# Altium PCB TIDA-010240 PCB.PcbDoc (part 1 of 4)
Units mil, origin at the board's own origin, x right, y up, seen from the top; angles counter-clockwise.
Board outline 5108.27 x 5374.02 mil, 4 copper layers (Top Layer, GND, PWR, Bottom Layer), stack 73.068 mil thick; 370 components, 162 nets, 1073 pads, 556 vias.
Unrouted connection lines stored in the file: 6.
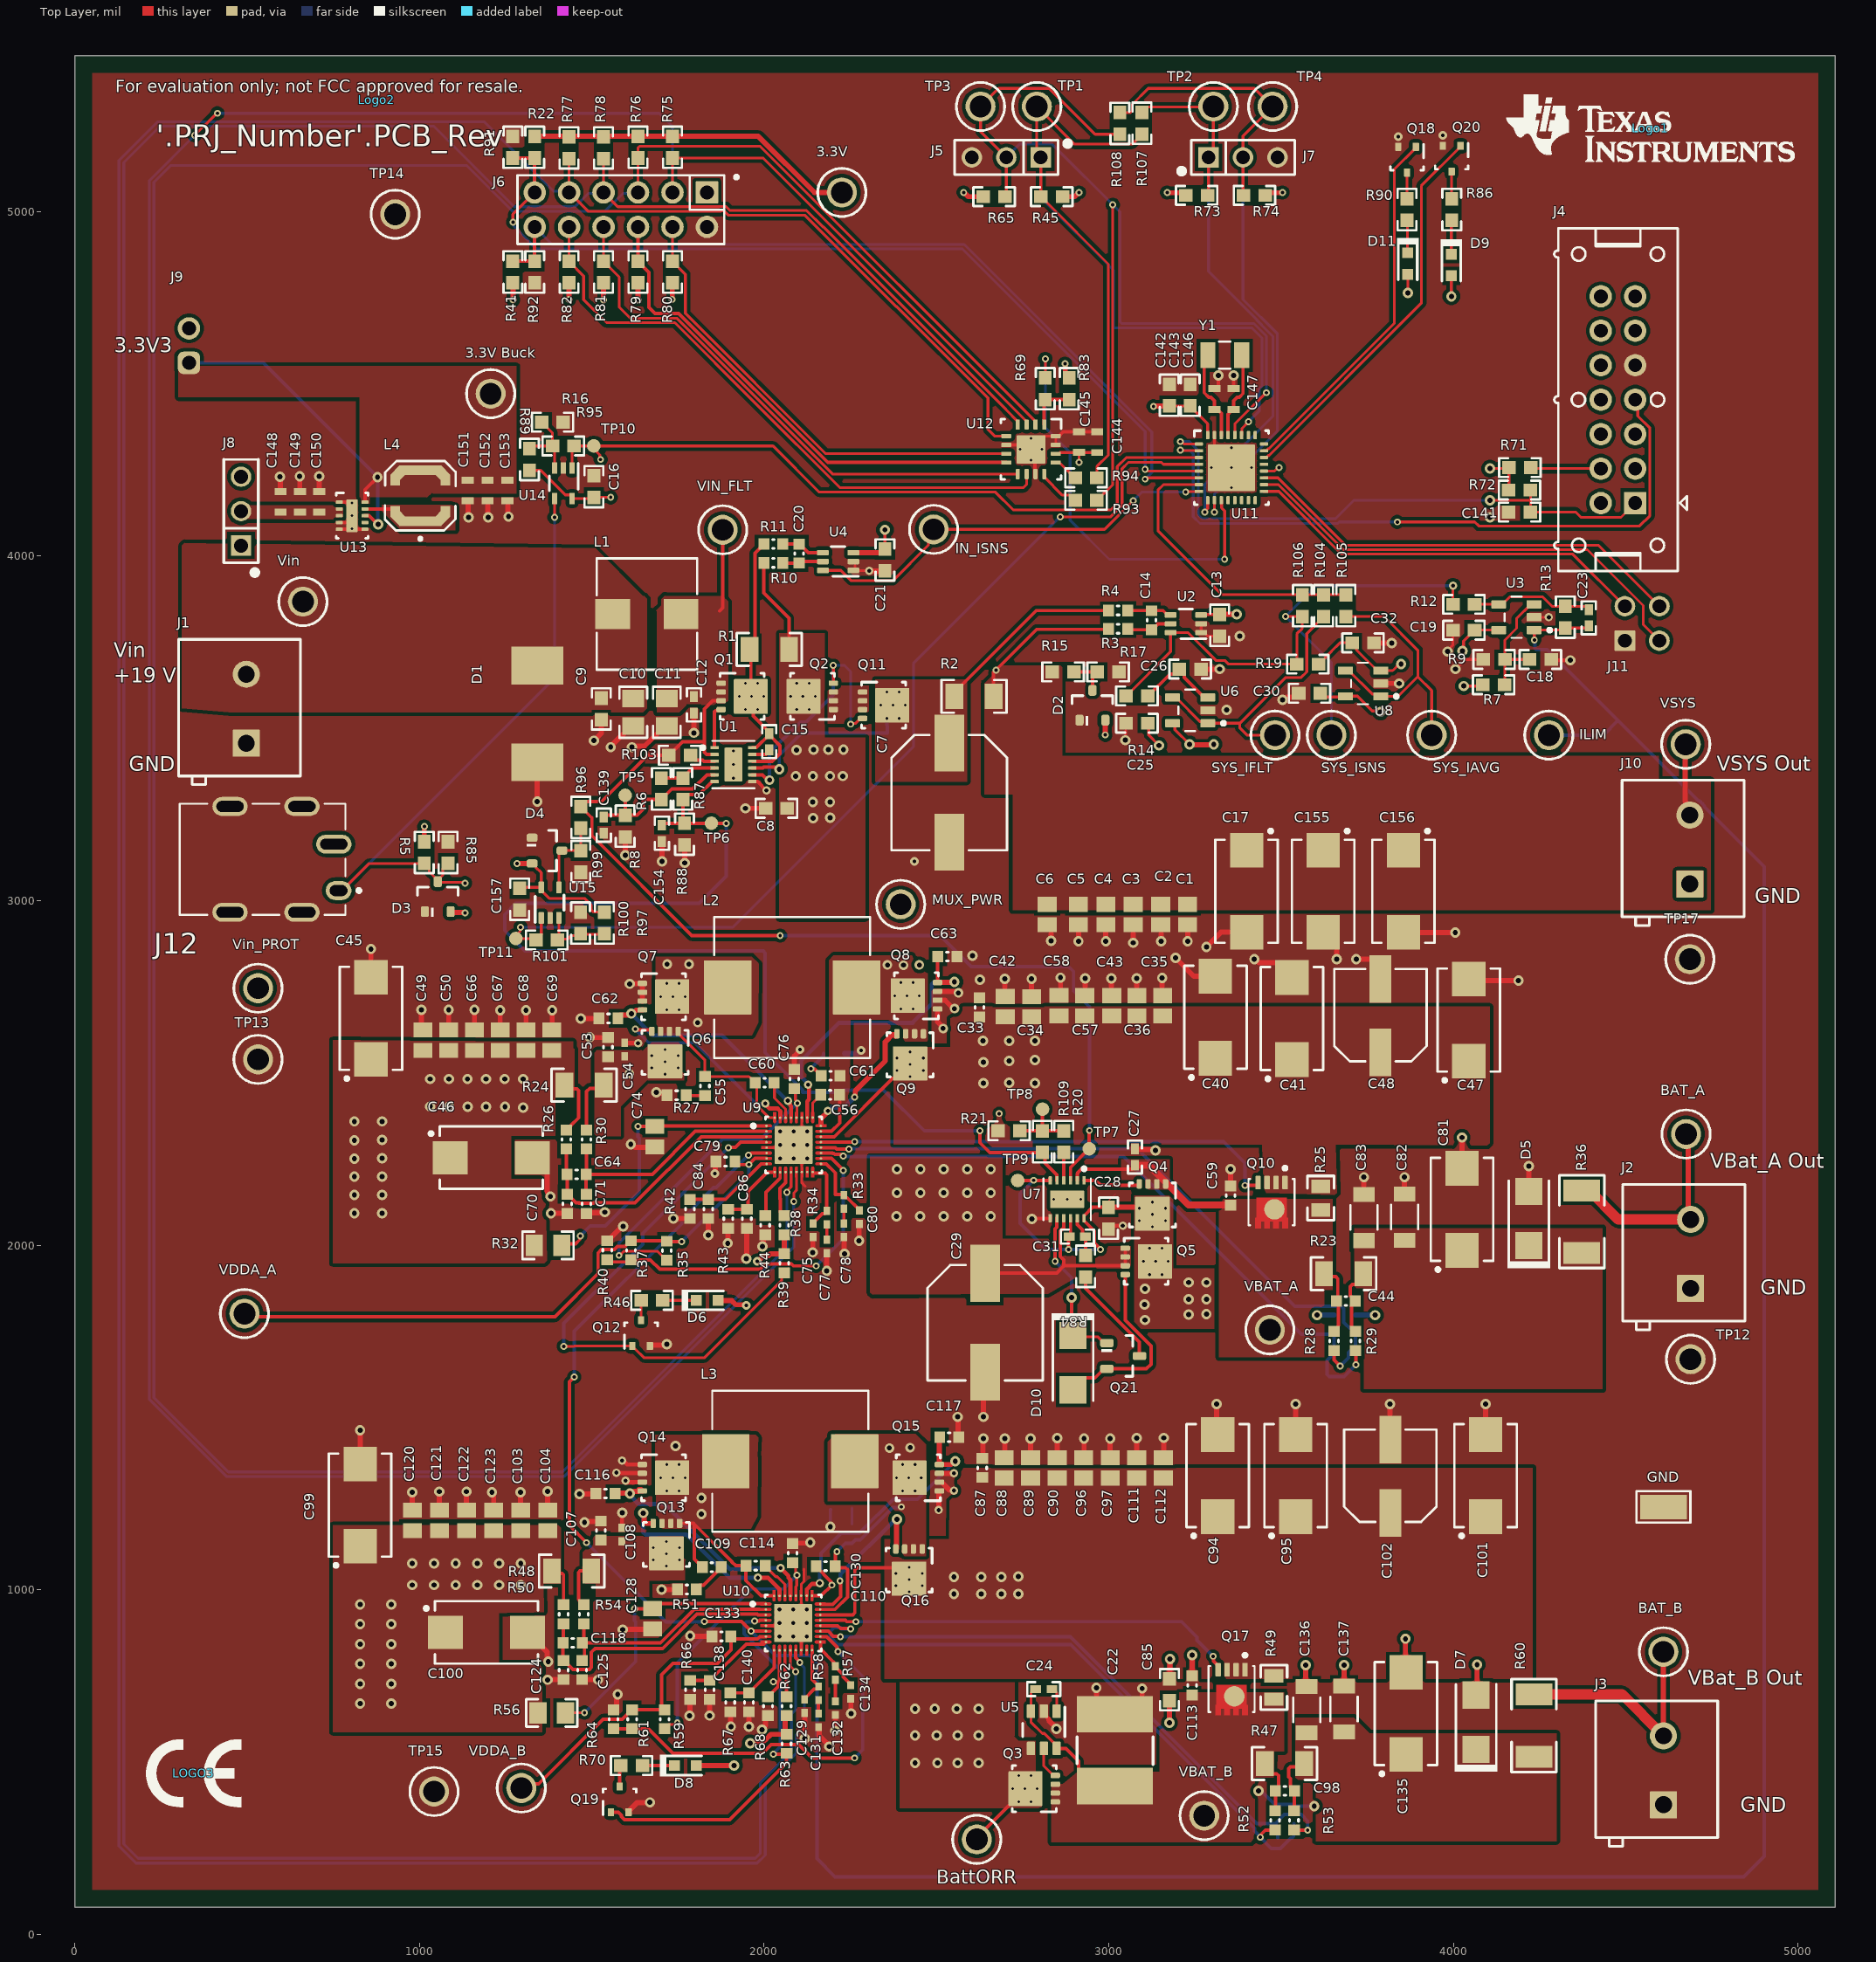
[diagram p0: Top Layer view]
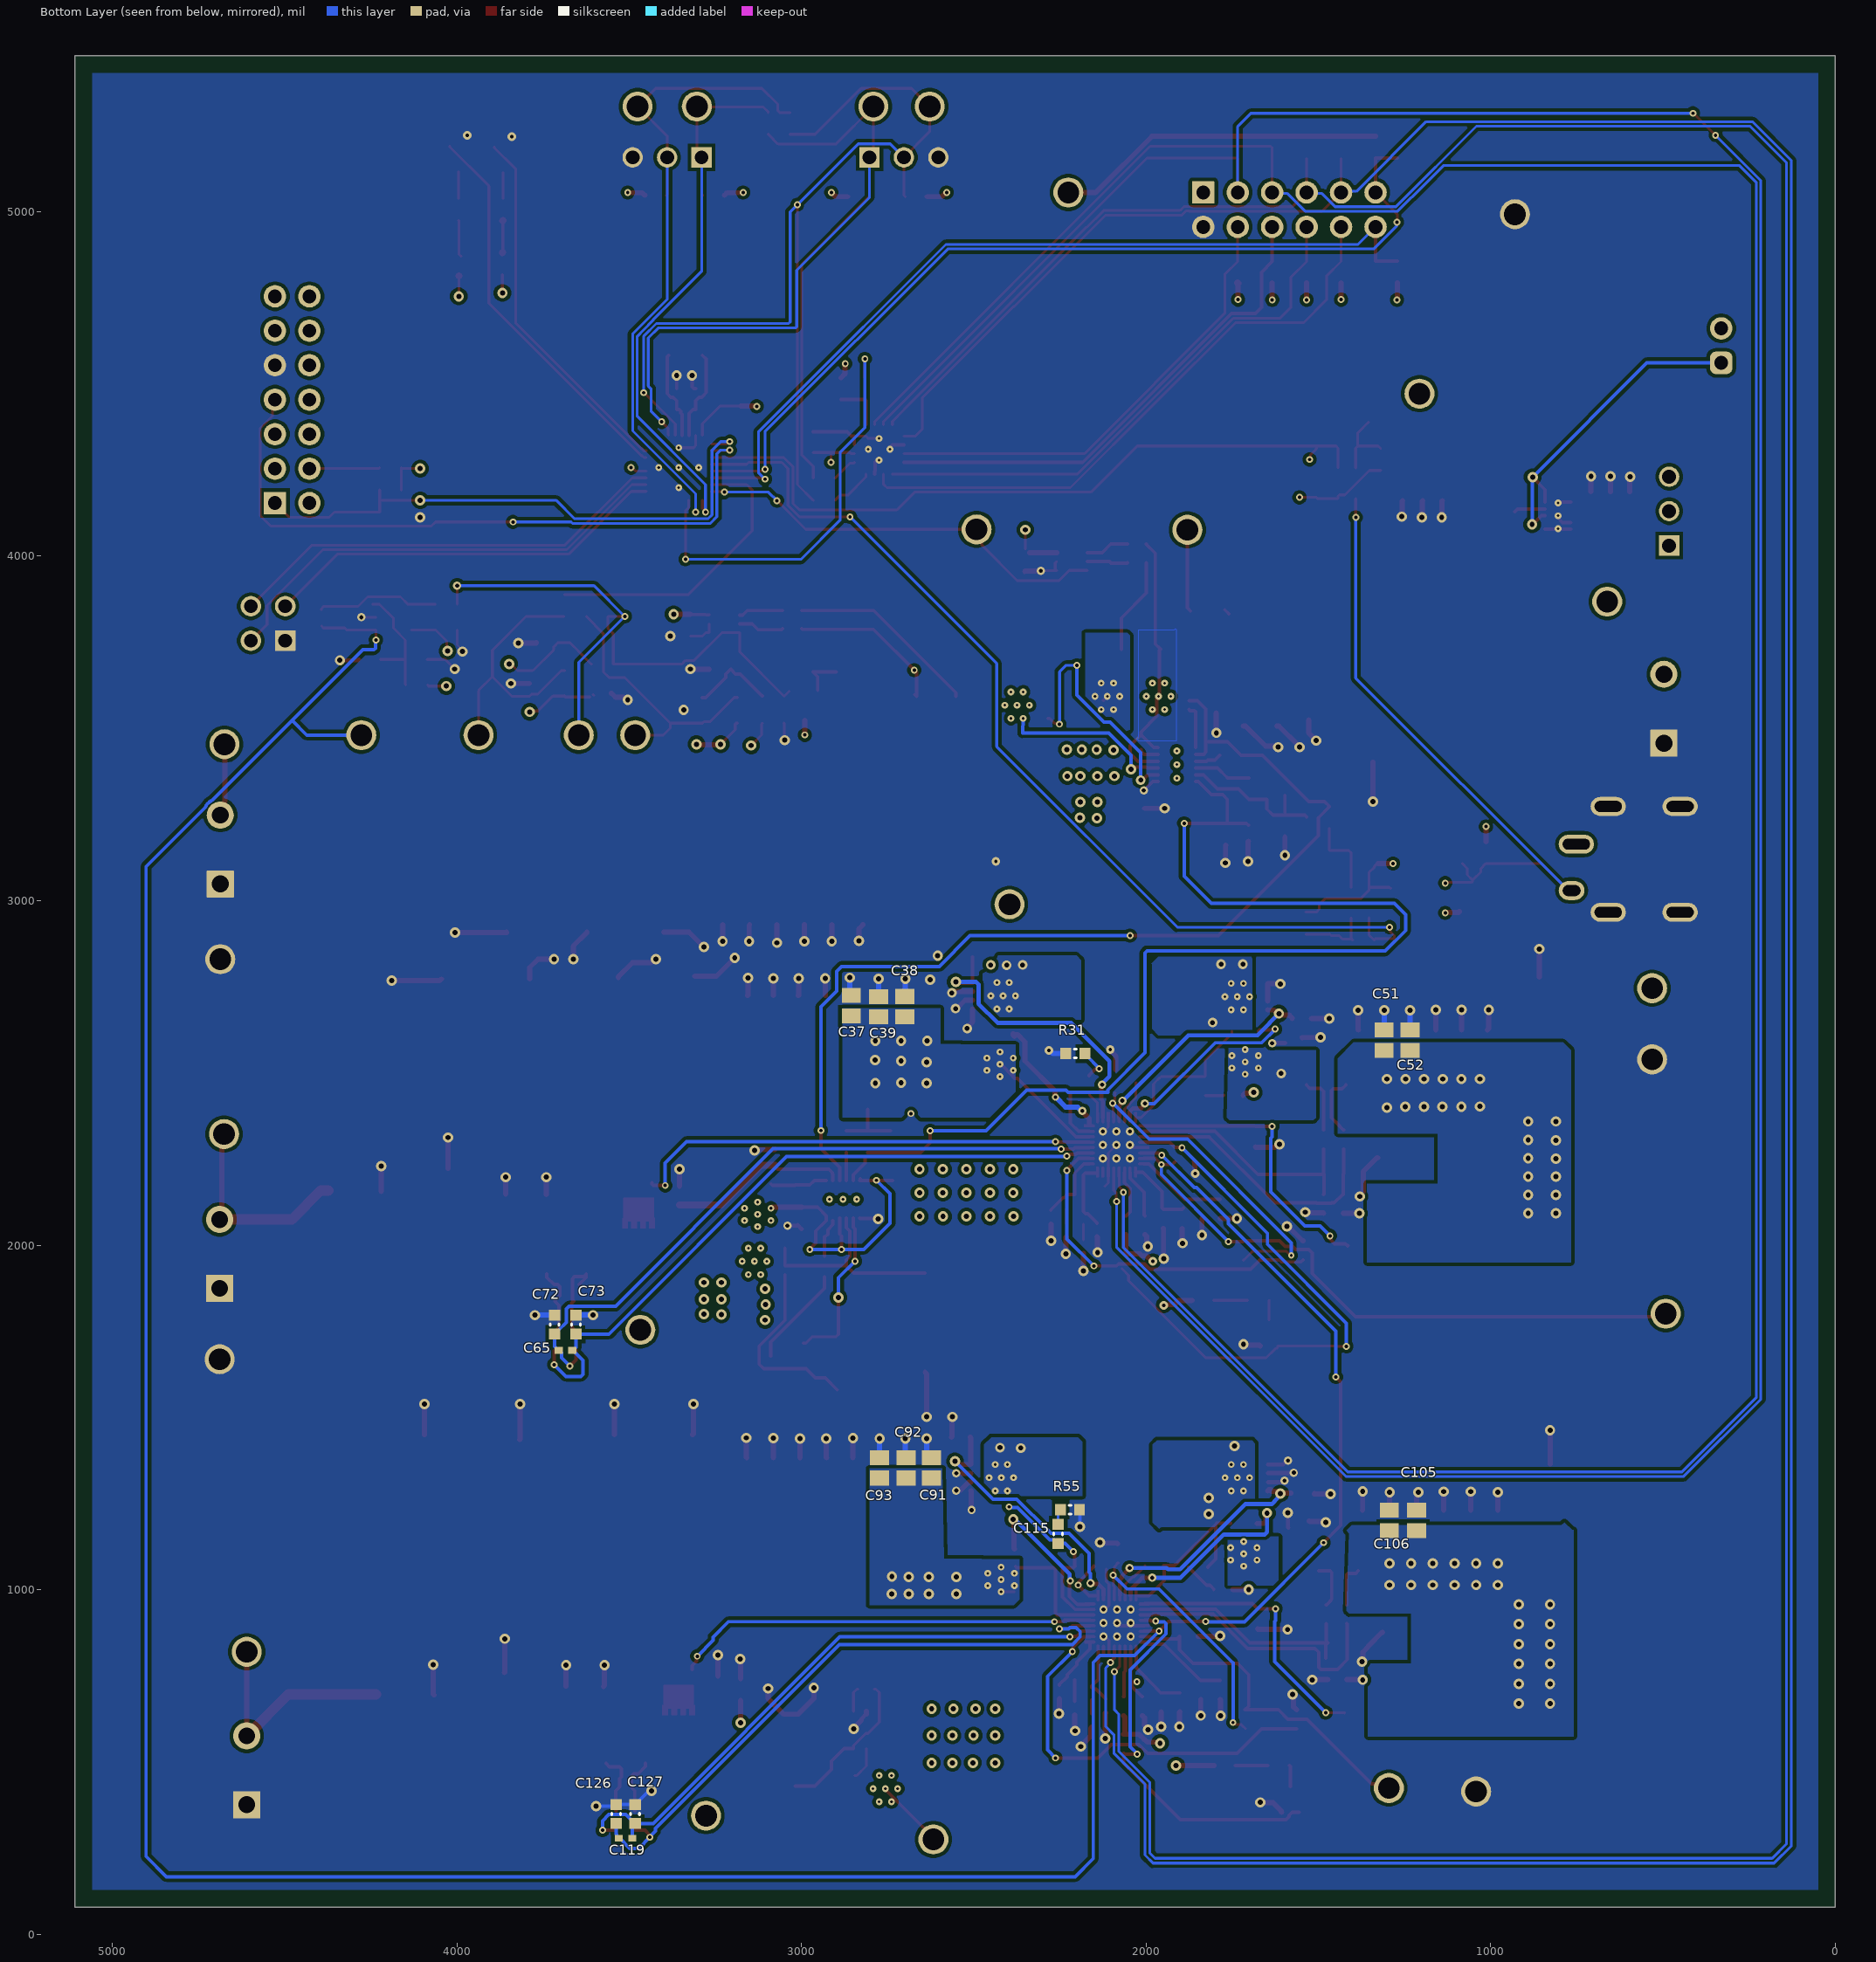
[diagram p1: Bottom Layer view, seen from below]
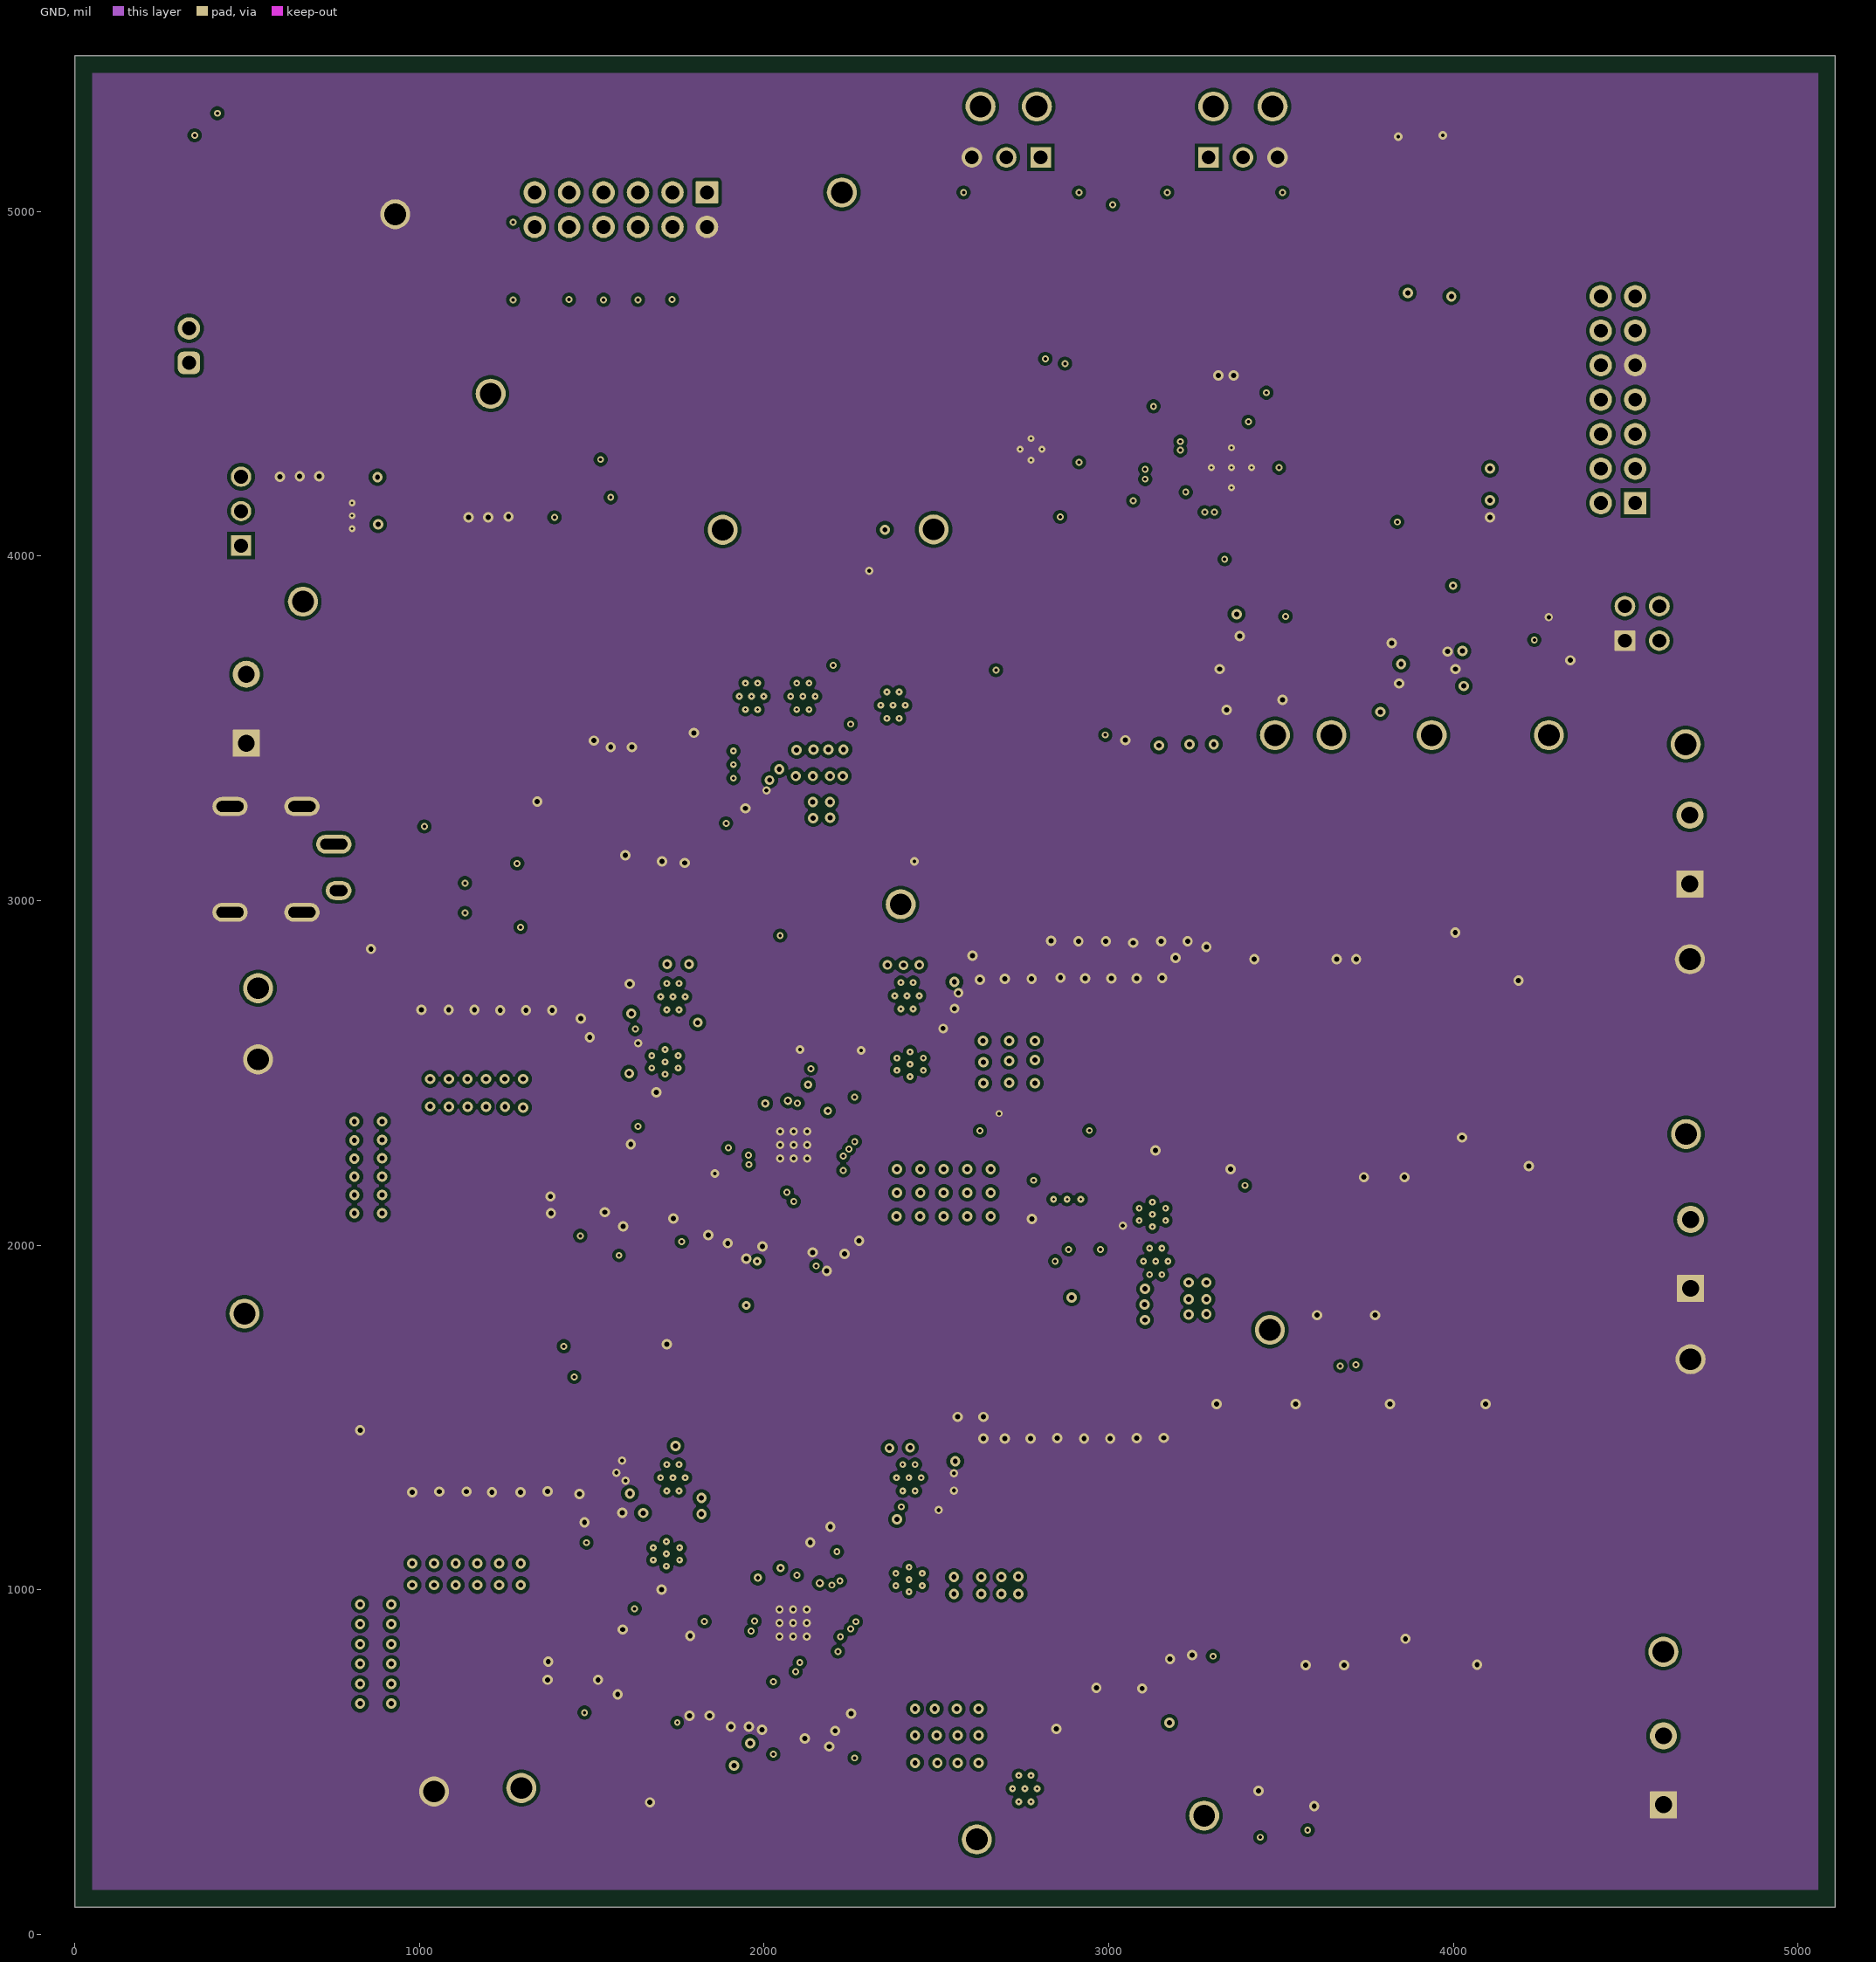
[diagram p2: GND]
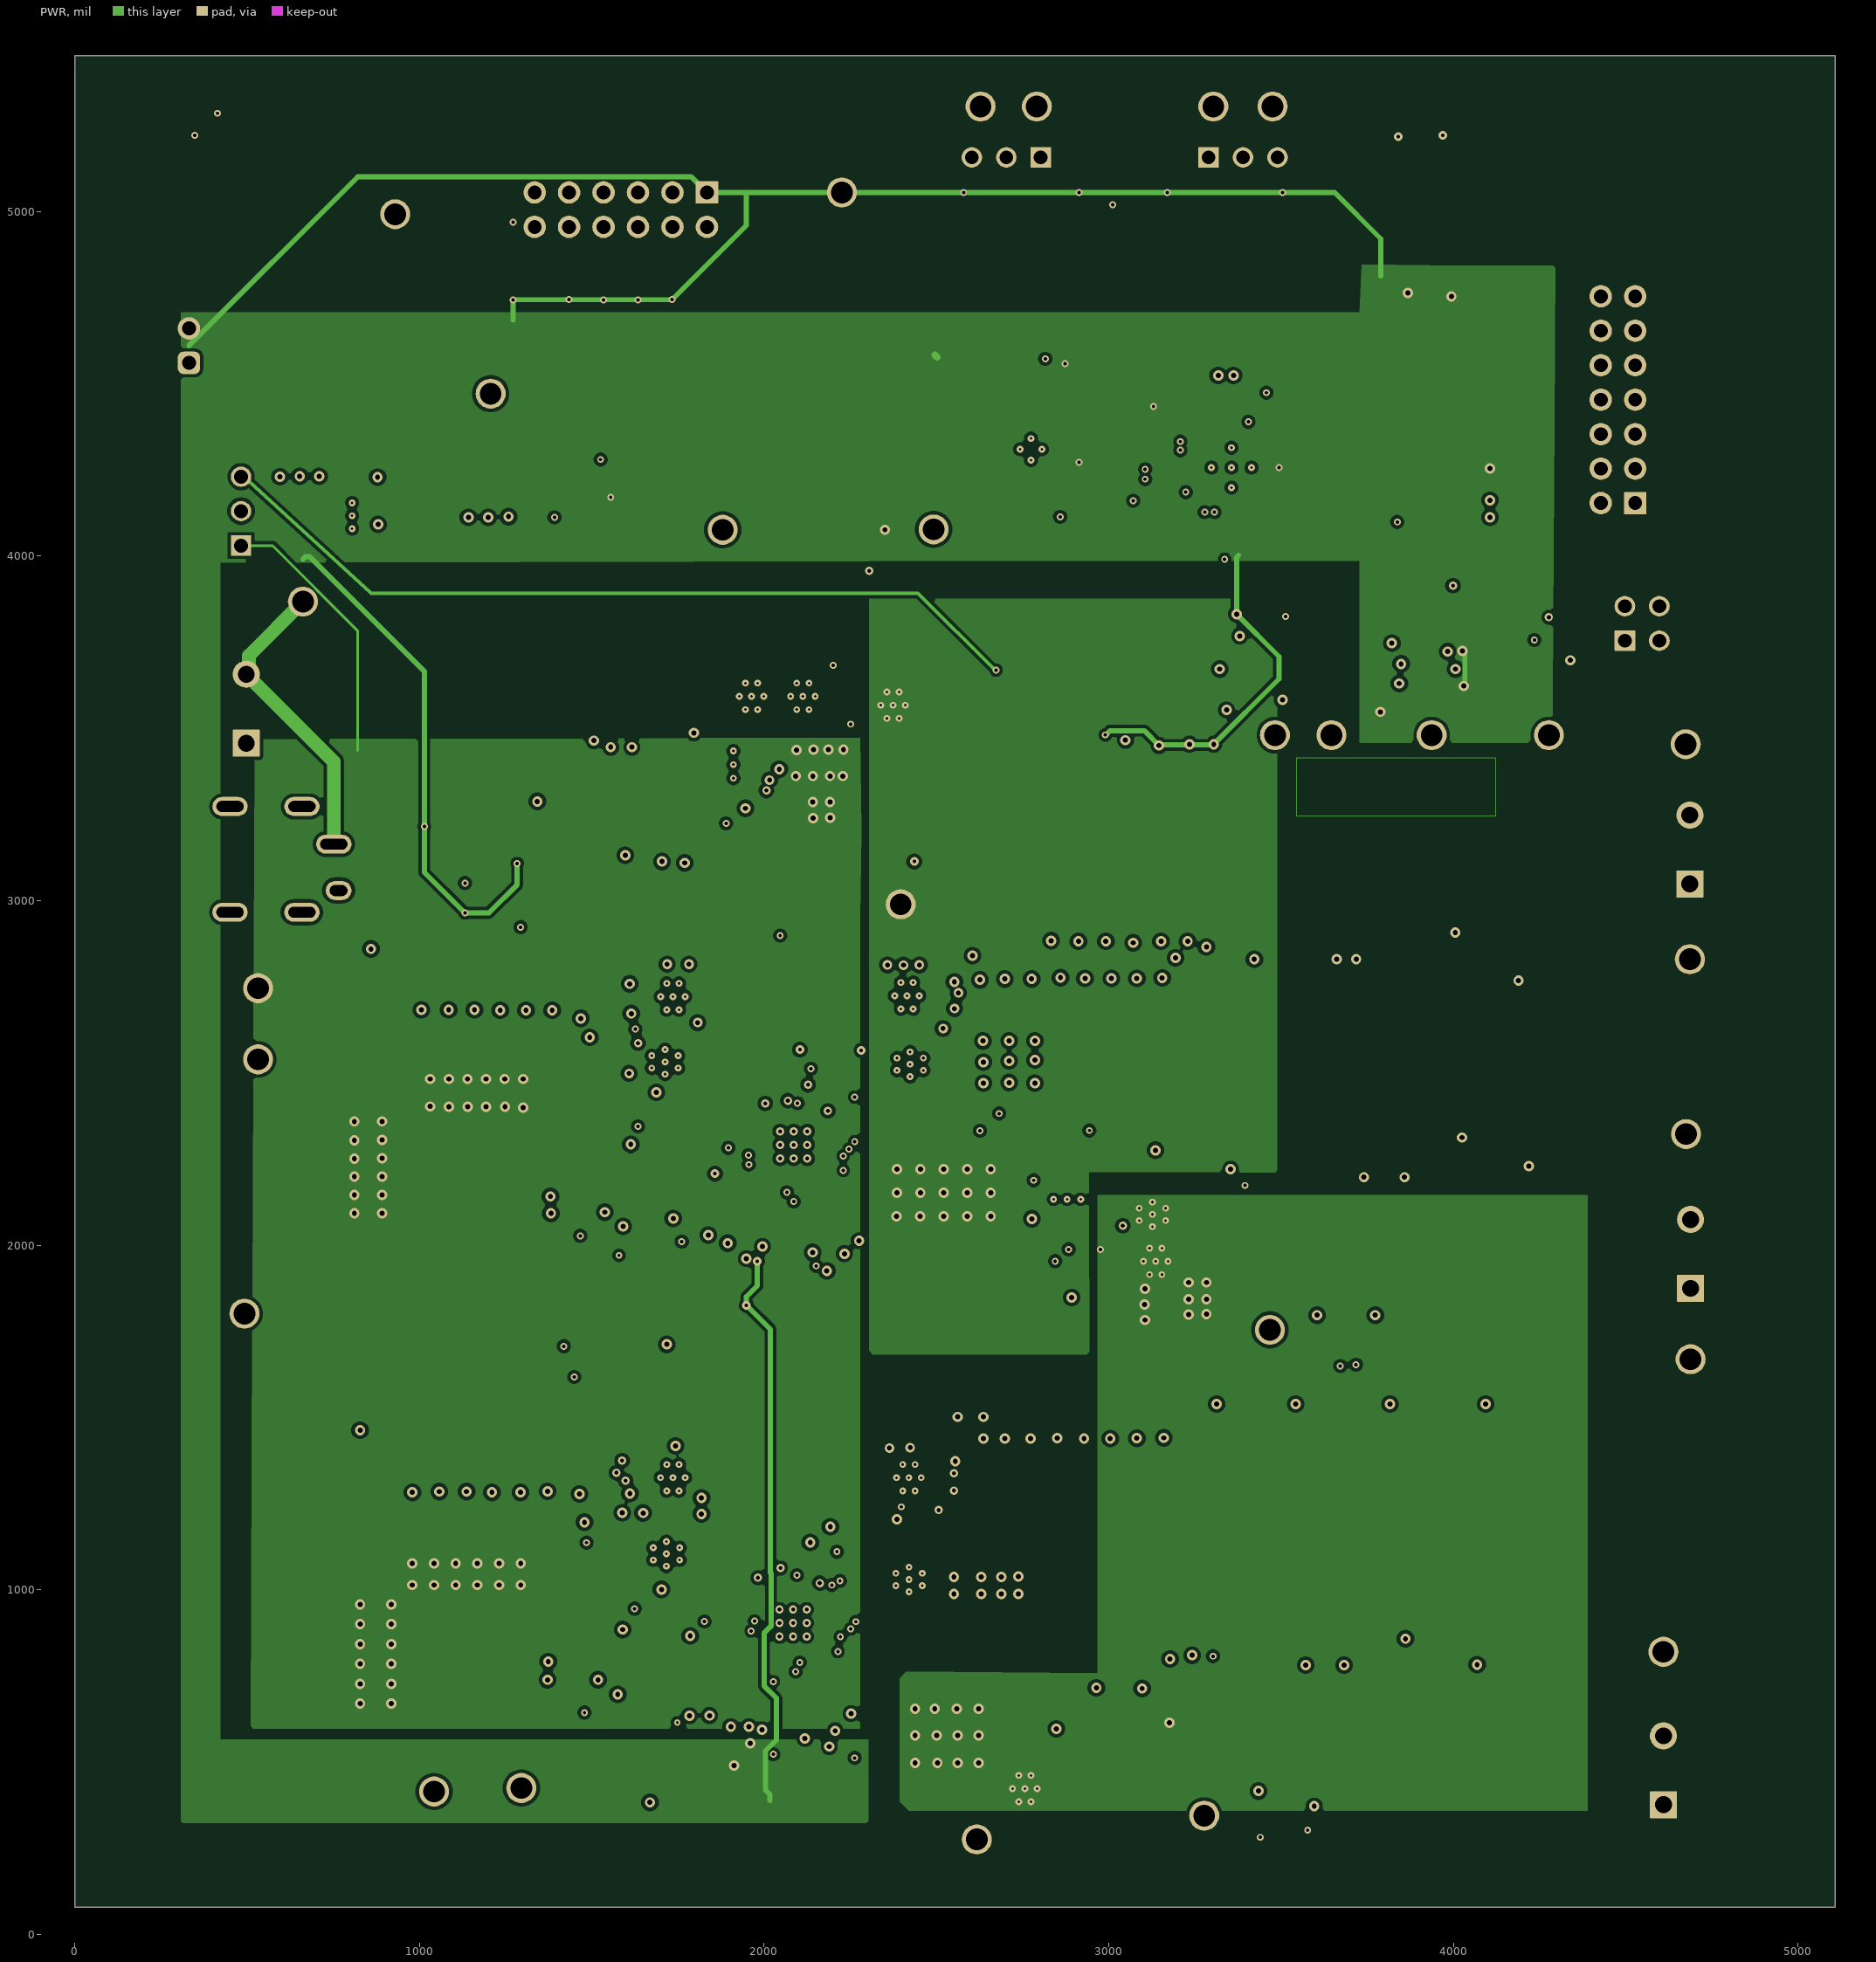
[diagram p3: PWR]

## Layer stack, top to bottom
Top Solder: solder mask 0.4, Solder Resist, Dk 3.5
Top Layer: signal copper 2.7559
Dielectric 1: prepreg 2.8, PP-006, Dk 4.1
GND: signal copper 1.378
Dielectric1: core 59.2, FR-4 High Tg, Dk 4.8
PWR: signal copper 1.378
Dielectric 2: prepreg 2.8, PP-006, Dk 4.1
Bottom Layer: signal copper 2.7559
Bottom Solder: solder mask 0.4, Solder Resist, Dk 3.5

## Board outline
0,78.74 0,5452.76 5108.27,5452.76 5108.27,78.74

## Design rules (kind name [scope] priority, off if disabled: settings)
AcuteAngle [All] p1: minimum=4.50000000000000E+0001 checktracksonly=FALSE
AssemblyTestPointUsage [All] p1: valid=2
BoardOutlineClearance BoardOutlineClearance_MountingHoles [OnCopper and InComponentClass('Mounting Holes')] p1: gap=39.37 ignorepadtopadclearanceinfootprint=FALSE
BoardOutlineClearance BoardOutlineClearance_Poly [OnCopper and IsPoly] p2: gap=50 ignorepadtopadclearanceinfootprint=FALSE
BoardOutlineClearance [OnCopper and Not InComponentClass('Logo') and not InComponentClass('FiducialMark') and not InRegion(1000,500,4000,800) and not InPoly] p3: gap=75 ignorepadtopadclearanceinfootprint=FALSE
Clearance Clearance_Keepouts [((IsTrack Or IsArc) And Not InPoly) And IsFree and IsKeepOut vs ((IsTrack Or IsArc) And Not InPoly) And IsFree and IsKeepOut] p1: gap=0 ignorepadtopadclearanceinfootprint=FALSE
Clearance Clearance_Poly [InPolygon] p2: gap=10 ignorepadtopadclearanceinfootprint=TRUE
Clearance Clearance_FiducialMark [IsKeepOut and InComponentClass('FiducialMark') vs IsPad and InComponentClass('FiducialMark')] p3: gap=0 ignorepadtopadclearanceinfootprint=FALSE
Clearance [All] p4: gap=5 ignorepadtopadclearanceinfootprint=TRUE
ComponentClearance ComponentClearance_MountingHoles_FiducialMarks [InComponentClass('Mounting Holes') vs InComponentClass('FiducialMark')] p1: gap=50 collisioncheckmode=3 verticalgap=10 showdistances=FALSE
ComponentClearance ComponentClearance_Shunt [InComponentClass('Header') vs InComponentClass('Shunt')] p2: gap=0 collisioncheckmode=3 verticalgap=0 showdistances=FALSE
ComponentClearance ComponentClearance_Logo [InComponentClass('Logo')] p3: gap=50 collisioncheckmode=3 verticalgap=10 showdistances=FALSE
ComponentClearance ComponentClearance_ScrewToNut [(HasFootprint('NY PMS 440 0025 PH')) vs (HasFootprint('Keystone_1902C'))] p4: gap=5 collisioncheckmode=3 verticalgap=10 showdistances=FALSE
ComponentClearance ComponentClearance_MountingHoles [InComponentClass('Mounting Holes')] p5: gap=250 collisioncheckmode=3 verticalgap=100000 showdistances=FALSE
ComponentClearance ComponentClearance_SmallPassives [HasFootprint('0201*') or HasFootprint('0402*') or HasFootprint('0508') or HasFootprint('0603*') or HasFootprint('0612') or HasFootprint('0805*') or HasFootprint('0815*') or HasFootprint('0830*') or HasFootprint('1206*') or HasFootprint('1210*') or HasFootprint('1808*') or HasFootprint('1812*') or HasFootprint('1825*') or HasFootprint('2010*') or HasFootprint('2220*') or HasFootprint('2225*') or HasFootprint('2512*') or HasFootprint('2728*') or HasFootprint('3518*') vs HasFootprint('0201*') or HasFootprint('0402*') or HasFootprint('0508') or HasFootprint('0603*') or HasFootprint('0612') or HasFootprint('0805*') or HasFootprint('0815*') or HasFootprint('0830*') or HasFootprint('1206*') or HasFootprint('1210*') or HasFootprint('1808*') or HasFootprint('1812*') or HasFootprint('1825*') or HasFootprint('2010*') or HasFootprint('2220*') or HasFootprint('2225*') or HasFootprint('2512*') or HasFootprint('2728*') or HasFootprint('3518*')] p6: gap=14.96 collisioncheckmode=3 verticalgap=10 showdistances=FALSE
ComponentClearance ComponentClearance_THtoSMT [IsThruComponent vs IsSMTComponent] p7: gap=40 collisioncheckmode=3 verticalgap=30 showdistances=FALSE
ComponentClearance ComponentClearance_THtoTH [IsThruComponent vs IsThruComponent] p8: gap=30 collisioncheckmode=3 verticalgap=30 showdistances=FALSE
ComponentClearance [All] p9: gap=30 collisioncheckmode=3 verticalgap=10 showdistances=FALSE
DiffPairsRouting [All] p1: maxlimit=100 minlimit=10 mostfreqgap=10 toplayer_minwidth=15 toplayer_maxwidth=15 toplayer_prefwidth=15 midlayer1_minwidth=15 midlayer1_maxwidth=15 midlayer1_prefwidth=15 midlayer2_minwidth=15 midlayer2_maxwidth=15 midlayer2_prefwidth=15 bottomlayer_minwidth=15 bottomlayer_maxwidth=15 bottomlayer_prefwidth=15 maxuncoupledlength=1000
FabricationTestPointUsage TestPointUsage [All] p1: valid=2 allowmultiple=FALSE
FabricationTestpoint Testpoint [All] p1: side=3 testpointundercomponent=TRUE minsize=40 maxsize=100 preferedsize=60 minholesize=0 maxholesize=40 preferedholesize=32 testpointgrid=1 allowsidetop=TRUE allowsidebottom=TRUE usegrid=TRUE gridtolerance=0.01
FanoutControl Fanout_LCC [IsLCC] p1: bgadir=Out bgaviamode=Centered fanoutstyle=Auto fanoutdirection=Alternating viagrid=1 // Fanout_LCC (Default Rule)
FanoutControl Fanout_BGA [IsBGA] p2: bgadir=Out bgaviamode=Centered fanoutstyle=Auto fanoutdirection=Alternating viagrid=1 // Fanout_BGA (Default Rule)
FanoutControl Fanout_Default [All] p4: bgadir=Out bgaviamode=Centered fanoutstyle=Auto fanoutdirection=Alternating viagrid=1 // Fanout_Default (Default Rule)
FanoutControl Fanout_Small [(CompPinCount < 5)] p5: bgadir=Out bgaviamode=Centered fanoutstyle=Auto fanoutdirection=OutThenIn viagrid=1 // Fanout_Small (Default Rule)
HoleSize [All] p1: absolutevalues=TRUE maxlimit=251 minlimit=7.87 maxpercent=80.000 minpercent=20.000
MinimumAnnularRing MinimumAnnularRing_ThermalPadVias [IsVia and InAnyComponent] p1: minimumring=5.91
MinimumAnnularRing [All] p2: minimumring=4
MinimumSolderMaskSliver MinimumSolderMaskSliver_Logo [InComponentClass('Logo') vs InComponentClass('Logo')] p1: minsoldermaskwidth=0.7
MinimumSolderMaskSliver [All] p2: minsoldermaskwidth=1.5
PlaneClearance [All] p1: clearance=10
PlaneConnect [All] p1: planeconnectstyle=Relief reliefexpansion=10 reliefentries=4 reliefconductorwidth=10 reliefairgap=10
PolygonConnect [All] p1: connectstyle=Direct reliefconductorwidth=10 reliefentries=4 polygonreliefangle="90 Angle" airgapwidth=10
RoutingVias ThermalPadVias [IsVia and InAnyComponent] p1: holewidth=7.87 width=19.68 viastyle="Through Hole" minholewidth=7.87 minwidth=19.68 maxholewidth=12.99 maxwidth=23.62
RoutingVias [All] p2: holewidth=10 width=18 viastyle="Through Hole" minholewidth=8 minwidth=18 maxholewidth=40 maxwidth=64
SMDEntry [All] p1 off: side=TRUE corner=TRUE anyangle=FALSE
SMDToCorner [All] p1 off: distance=50000
SilkToBoardRegionClearance [Not ((IsComment or IsDesignator) And (Hide <> 'False')) and not InRegion(1000,500,4000,800)] p1:
SilkToSilkClearance SilkToSilkClearance_Pb-FreeLogo [(HasFootprint('Pb-Free_Overlay_Medium') OR HasFootprint('Pb-Free_Overlay_Small')) vs (HasFootprint('Pb-Free_Overlay_Medium') OR HasFootprint('Pb-Free_Overlay_Small'))] p1: silktosilkclearance=0
SilkToSilkClearance [All] p2: silktosilkclearance=0
SilkToSolderMaskClearance SilkToComponentPadClearance [(IsPad or IsFill or IsRegion) and InAnycomponent] p1: minsilkscreentomaskgap=5 clearancetoexposedcopper=TRUE
SilkToSolderMaskClearance "Silk to Solder Mask Opening" [All] p2: minsilkscreentomaskgap=3.94 clearancetoexposedcopper=FALSE
SolderMaskExpansion [All] p1: expansion=4 istentingtop=FALSE
UnRoutedNet [All] p1: checkbadconnections=TRUE
Width [All] p1: maxlimit=100 minlimit=5 preferedwidth=10 checkconnectedcopper=TRUE
13 further rules are at their usual default settings.

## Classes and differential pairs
component class Sensing: C13 C14 C16 C18 C19 C20 C21 C23 C25 C26 C30 C32 C157 D2 D3 D4 ILIM IN_ISNS R3 R4 R5 R7 R9 R10 R11 R12 R13 R14 R15 R16 R17 R19 R85 R89 R95 R96 R97 R99 R100 R101 R104 R105 R106 SYS_IAVG SYS_IFLT SYS_ISNS TP10 TP11 U2 U3 U4 U6 U8 U14 U15
component class BQ25731_A: BAT_A C33 C34 C35 C36 C37 C38 C39 C40 C41 C42 C43 C44 C45 C46 C47 C48 C49 C50 C51 C52 C53 C54 C55 C56 C57 C58 C59 C60 C61 C62 C63 C64 C65 C66 C67 C68 C69 C70 C71 C72 C73 C74 C75 C76 C77 C78 C79 C80 C81 C82 C83 C84 C86 D5 D6 GND J2 L2 Q6 Q7 Q8 Q9 Q10 Q12 R23 R24 R25 R26 R27 R28 R29 R30 R31 R32 R33 R34 R35 R36 R37 R38 R39 R40 R42 R43 R44 R46 TP24 TP34 U9 VDDA_A
component class MSP: 3.3V "3.3V Buck" C141 C142 C143 C144 C145 C146 C147 C148 C149 C150 C151 C152 C153 D9 D11 J4 J5 J6 J7 J8 J9 J11 L4 Q18 Q20 R22 R41 R45 R65 R69 R71 R72 R73 R74 R75 R76 R77 R78 R79 R80 R81 R82 R83 R86 R90 R91 R92 R93 R94 R107 R108 TP1 TP2 TP3 TP4 TP12 TP13 TP14 TP15 TP17 U11 U12 U13 Y1
component class Header: J5 J6 J7 J8 J9
component class BQ25731_B: BAT_B C87 C88 C89 C90 C91 C92 C93 C94 C95 C96 C97 C98 C99 C100 C101 C102 C103 C104 C105 C106 C107 C108 C109 C110 C111 C112 C113 C114 C115 C116 C117 C118 C119 C120 C121 C122 C123 C124 C125 C126 C127 C128 C129 C130 C131 C132 C133 C134 C135 C136 C137 C138 C140 D7 D8 J3 L3 Q13 Q14 Q15 Q16 Q17 Q19 R47 R48 R49 R50 R51 R52 R53 R54 R55 R56 R57 R58 R59 R60 R61 R62 R63 R64 R66 R67 R68 R70 TP52 U10 VDDA_B z
component class InputProtection: BattORR C1 C2 C3 C4 C5 C6 C7 C8 C9 C10 C11 C12 C15 C17 C22 C24 C27 C28 C29 C31 C85 C139 C154 C155 C156 D1 D10 J1 J10 J12 L1 MUX_PWR Q1 Q2 Q3 Q4 Q5 Q11 Q21 R1 R2 R6 R8 R20 R21 R84 R87 R88 R103 R109 TP5 TP6 TP7 TP8 TP9 U1 U5 U7 VBAT_A VBAT_B Vin VIN_FLT Vin_PROT VSYS
component class Logo: Logo1
component class PCB_Project_Hardware: Logo1 Logo2 LOGO3 ZZ1 ZZ2 ZZ3 ZZ4
component class AssemblyNote: ZZ1 ZZ2 ZZ3 ZZ4

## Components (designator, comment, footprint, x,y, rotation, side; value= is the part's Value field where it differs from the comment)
3.3V "5010" Keystone5010 2225.55,5055.64 r0 top
"3.3V Buck" "5010" Keystone5010 1206.57,4471.63 r0 top
BAT_A "5010" Keystone5010 4675.2,2322.83 r0 top
BAT_B "5010" Keystone5010 4609.54,820.17 r0 top
BattORR "5010" Keystone5010 2617.03,275.57 r90 top
C1 "GRM21BR6YA106KE43L" 0805L 3228.85,2959.92 r270 top value=10uF
C2 "GRM21BR6YA106KE43L" 0805L 3150.54,2959.92 r270 top value=10uF
C3 "GRM21BR6YA106KE43L" 0805L 3071.05,2959.92 r270 top value=10uF
C4 "GRM21BR6YA106KE43L" 0805L 2991.57,2959.92 r270 top value=10uF
C5 "GRM21BR6YA106KE43L" 0805L 2912.09,2959.92 r270 top value=10uF
C6 "GRM21BR6YA106KE43L" 0805L 2821.25,2959.92 r270 top value=10uF
C7 "EMVA630ADA470MHA0G" CAPSMT_62_HA0 2537.15,3313.76 r270 top value=47uF
C8 "GRM188R72A104KA35J" 0603 2035.64,3268.16 r180 top value=0.1uF
C9 "GRM188R71H152KA01D" 0603 1527.61,3556.62 r270 top value=1500pF
C10 "NMC0805X5R226M35TRPLPF" 0805_HV 1620.49,3546.78 r270 top value=22uF
C11 "NMC0805X5R226M35TRPLPF" 0805_HV 1717.83,3546.78 r270 top value=22uF
C12 "GCM155R71H104KE02D" 0402 1796.38,3568.43 r270 top value=0.1uF
C13 "C0603C104K9RAC7867" 0603 3321.93,3799.4 r270 top value=0.1uF
C14 "C0603C103J5RACTU" 0603L 3124.38,3813.93 r270 top value=0.01uF
C15 "GCM155R71H104KE02D" 0402 2014.83,3461.64 r270 top value=0.1uF
C16 "C0603C104K9RAC7867" 0603 1505.91,4201.78 r90 top value=0.1uF
C17 "T521D336M035ATE065" 7343-31 3399.88,3027.59 r270 top value=33uF
C18 "C0603C104K9RAC7867" 0603 4252.53,3700.04 r0 top value=0.1uF
C19 "C0603C104K9RAC7867" 0603 4030.34,3785.38 r180 top value=0.1uF
C20 "C0603C103J5RACTU" 0603L 2101.63,4007.48 r270 top value=0.01uF
C21 "C0603C104K9RAC7867" 0603 2350.64,3988.78 r270 top value=0.1uF
C22 "KCM55WR7YA336MH01K" KCM55W 3018.25,534.63 r90 top value=33uF
C23 "GRM155R70J103KA01D" 0402 4393.02,3821 r270 top value=0.01uF
C24 "GCM155R71H104KE02D" 0402 2811.56,711.8 r0 top value=0.1uF
C25 "C0603C104K9RAC7867" 0603 3081.77,3515.1 r180 top value=0.1uF
C26 "C0603C103K4RACTU" 0603 3236.3,3672.04 r0 top value=0.01uF
C27 "GCM155R71H104KE02D" 0402 3076.02,2255.96 r90 top value=0.1uF
C28 "GRM188R72A104KA35J" 0603 2999.26,2078.74 r270 top value=0.1uF
C29 "EMVA630ADA470MHA0G" CAPSMT_62_HA0 2641.15,1775.17 r270 top value=47uF
C30 "C0603C104K9RAC7867" 0603 3582.68,3601.88 r180 top value=0.1uF
C31 "GCM155R71H104KE02D" 0402 2909.03,2025.17 r0 top value=0.1uF
C32 "GRM188R60J106ME84" 0603 3737.83,3748.6 r0 top value=10uF
C33 "C0603C103J5RACTU" 0603L 2625.18,2690.54 r90 top value=0.01uF
C34 "GRM21BR6YA106KE43L" 0805L 2776.14,2692.36 r90 top value=10uF
C35 "GRM21BR6YA106KE43L" 0805L 3156.39,2695.08 r90 top value=10uF
C36 "GRM21BR6YA106KE43L" 0805L 3081.57,2695.08 r90 top value=10uF
C37 "GRM21BR6YA106KE43L" 0805L 2855.27,2695.16 r90 bottom value=10uF
C38 "GRM21BR6YA106KE43L" 0805L 2699.82,2692.49 r90 bottom value=10uF
C39 "GRM21BR6YA106KE43L" 0805L 2776.14,2692.36 r90 bottom value=10uF
C40 "T521D336M035ATE065" 7343-31 3309.59,2661.93 r90 top value=33uF
C41 "T521D336M035ATE065" 7343-31 3531.48,2657.91 r90 top value=33uF
C42 "GRM21BR6YA106KE43L" 0805L 2699.82,2692.49 r90 top value=10uF
C43 "GRM21BR6YA106KE43L" 0805L 3008.86,2695.08 r90 top value=10uF
C44 "CGA3E2X7R1H104K080AA" 0603L 3687.82,1838.45 r0 top value=0.1uF
C45 "T521D336M035ATE065" 7343-31 859.27,2658.66 r90 top value=33uF
C46 "T521D336M035ATE065" 7343-31 1208.29,2254.25 r0 top value=33uF
C47 "T521D336M035ATE065" 7343-31 4044.76,2653.59 r90 top value=33uF
C48 "Cap_Polarized" CAPSMT_62_F61 3789.37,2665.42 r90 top value=47uF
C49 "GRM21BR6YA106KE43L" 0805L 1009.89,2595.11 r90 top value=10uF
C50 "GRM21BR6YA106KE43L" 0805L 1084.69,2595.11 r90 top value=10uF
C51 "GRM21BR6YA106KE43L" 0805L 1309.1,2595.11 r90 bottom value=10uF
C52 "GRM21BR6YA106KE43L" 0805L 1234.3,2595.11 r90 bottom value=10uF
C53 "C0603C103J5RACTU" 0603L 1547.2,2574.97 r90 top value=0.01uF
C54 "C1005NP01H102J050BA" 0402L 1595.53,2567.85 r90 top value=1000pF
C55 "Capacitor" 0603L 1828.29,2462.09 r270 top value=330pF
C56 "Capacitor" 0603L 2191.75,2436.92 r0 top value=0.047uF
C57 "GRM21BR6YA106KE43L" 0805L 2930.12,2695.08 r90 top value=10uF
C58 "GRM21BR6YA106KE43L" 0805L 2855.27,2695.16 r90 top value=10uF
C59 "CGA3E1X7R1V105K080AC" 0603L 3353.6,2144.16 r90 top value=1uF
C60 "Capacitor" 0603L 2001.42,2471.93 r180 top value=0.047uF
C61 "Capacitor" 0603L 2192.73,2491.9 r180 top value=330pF
C62 "Capacitor" 0603L 1548.29,2658.46 r180 top value=150pF
C63 "Capacitor" 0603L 2531.71,2837.84 r180 top value=150pF
C64 "C0603C103J5RACTU" 0603L 1455.97,2205.9 r0 top value=0.01uF
C65 "CGA2B3X7R1H683K050BB" 0402L 3684.22,1694.94 r180 bottom value=0.068uF
C66 "GRM21BR6YA106KE43L" 0805L 1159.5,2595.11 r90 top value=10uF
C67 "GRM21BR6YA106KE43L" 0805L 1234.3,2595.11 r90 top value=10uF
C68 "GRM21BR6YA106KE43L" 0805L 1309.1,2595.11 r90 top value=10uF
C69 "GRM21BR6YA106KE43L" 0805L 1383.9,2595.11 r90 top value=10uF
C70 "GRM188R71H333KA61D" 0603L 1428.41,2120.12 r270 top value=0.033uF
C71 "GRM188R71H333KA61D" 0603L 1484.38,2120.12 r270 top value=0.033uF
C72 "GRM188R71H183KA01D" 0603L 3715.87,1769.74 r90 bottom value=0.018uF
C73 "GRM188R71H183KA01D" 0603L 3653.86,1769.74 r90 bottom value=0.018uF
C74 "C2012X7R1H474K125AB" 0805L 1683.07,2315.41 r270 top value=0.47uF
C75 "Capacitor" 0402L 2142.28,2043.71 r90 top value=33pF
C76 "Capacitor" 0603L 2087.79,2482.5 r90 top value=2.2uF
C77 "GRM155R71H472KA01D" 0402L 2181.95,1996.47 r90 top value=4700pF
C78 "Capacitor" 0402L 2231.4,2043.57 r270 top value=680pF
C79 "CGA3E1X7R1V105K080AC" 0603L 1887.7,2242.87 r180 top value=1uF
C80 "Capacitor" 0402L 2276.17,2081.57 r270 top value=15pF
C81 "T521D336M035ATE065" 7343-31 4025.07,2104.43 r90 top value=33uF
C82 "Capacitor" 1206_180 3858.33,2081.73 r90 top value=10uF
C83 "Capacitor" 1206_180 3740.47,2080.75 r90 top value=10uF
C84 "Capacitor" 0603L 1837.86,2105.35 r270 top value=100pF
C85 "CGA3E1X7R1V105K080AC" 0603 3176.07,710.23 r270 top value=1uF
C86 "Capacitor" 0603L 1950.06,2076.81 r270 top value=100pF
C87 "C0603C103J5RACTU" 0603L 2633.08,1353.91 r90 top value=0.01uF
C88 "GRM21BR6YA106KE43L" 0805L 2696.38,1353.91 r90 top value=10uF
C89 "GRM21BR6YA106KE43L" 0805L 2773.34,1353.91 r90 top value=10uF
C90 "GRM21BR6YA106KE43L" 0805L 2850.3,1353.91 r90 top value=10uF
C91 "GRM21BR6YA106KE43L" 0805L 2622.72,1353.91 r90 bottom value=10uF
C92 "GRM21BR6YA106KE43L" 0805L 2696.38,1353.91 r90 bottom value=10uF
C93 "GRM21BR6YA106KE43L" 0805L 2773.34,1353.91 r90 bottom value=10uF
C94 "T521D336M035ATE065" 7343-31 3316.12,1331.42 r90 top value=33uF
C95 "T521D336M035ATE065" 7343-31 3542.5,1331.42 r90 top value=33uF
C96 "GRM21BR6YA106KE43L" 0805L 2927.26,1353.91 r90 top value=10uF
C97 "GRM21BR6YA106KE43L" 0805L 3004.23,1353.91 r90 top value=10uF
C98 "CGA3E2X7R1H104K080AA" 0603L 3511.33,416.19 r0 top value=0.1uF
C99 "T521D336M035ATE065" 7343-31 827.72,1245.82 r90 top value=33uF
C100 "T521D336M035ATE065" 7343-31 1194.45,876.4 r0 top value=33uF
C101 "T521D336M035ATE065" 7343-31 4093.68,1331.42 r90 top value=33uF
C102 "Cap_Polarized" CAPSMT_62_F61 3818.09,1328.62 r90 top value=47uF
C103 "GRM21BR6YA106KE43L" 0805L 1293.86,1201.53 r90 top value=10uF
C104 "GRM21BR6YA106KE43L" 0805L 1372.5,1201.53 r90 top value=10uF
C105 "GRM21BR6YA106KE43L" 0805L 1215.22,1201.53 r90 bottom value=10uF
C106 "GRM21BR6YA106KE43L" 0805L 1293.86,1201.53 r90 bottom value=10uF
C107 "C0603C103J5RACTU" 0603L 1526.29,1172.07 r90 top value=0.01uF
C108 "C1005NP01H102J050BA" 0402L 1587.04,1160.26 r90 top value=1000pF
C109 "Capacitor" 0603L 1848.33,1065.76 r0 top value=330pF
C110 "Capacitor" 0603L 2178.58,1068.62 r0 top value=0.047uF
C111 "GRM21BR6YA106KE43L" 0805L 3081.19,1353.91 r90 top value=10uF
C112 "GRM21BR6YA106KE43L" 0805L 3158.15,1353.91 r90 top value=10uF
C113 "CGA3E1X7R1V105K080AC" 0603L 3242.09,722.75 r90 top value=1uF
C114 "Capacitor" 0603L 1975.65,1069.88 r180 top value=0.047uF
C115 "Capacitor" 0603L 2255.19,1162.21 r90 bottom value=330pF
C116 "Capacitor" 0603L 1539.44,1279.15 r180 top value=150pF
C117 "Capacitor" 0603L 2537.22,1443.11 r180 top value=150pF
C118 "C0603C103J5RACTU" 0603L 1444.42,845.98 r0 top value=0.01uF
C119 "CGA2B3X7R1H683K050BB" 0402L 3510.16,279.35 r180 bottom value=0.068uF
C120 "GRM21BR6YA106KE43L" 0805L 979.31,1201.53 r90 top value=10uF
C121 "GRM21BR6YA106KE43L" 0805L 1057.95,1201.53 r90 top value=10uF
C122 "GRM21BR6YA106KE43L" 0805L 1136.59,1201.53 r90 top value=10uF
C123 "GRM21BR6YA106KE43L" 0805L 1215.22,1201.53 r90 top value=10uF
C124 "GRM188R71H333KA61D" 0603L 1418.07,767.24 r270 top value=0.033uF
C125 "GRM188R71H333KA61D" 0603L 1471.98,767.24 r270 top value=0.033uF
C126 "GRM188R71H183KA01D" 0603L 3537.72,349.61 r90 bottom value=0.018uF
C127 "GRM188R71H183KA01D" 0603L 3482.6,349.61 r90 bottom value=0.018uF
C128 "C2012X7R1H474K125AB" 0805L 1676.51,916.11 r270 top value=0.47uF
C129 "Capacitor" 0402L 2117.43,662.33 r90 top value=33pF
C130 "Capacitor" 0603L 2082.97,1106.32 r90 top value=2.2uF
C131 "GRM155R71H472KA01D" 0402L 2157.78,621.22 r90 top value=4700pF
C132 "Capacitor" 0402L 2207,656.65 r270 top value=680pF
C133 "CGA3E1X7R1V105K080AC" 0603L 1875.89,864.68 r180 top value=1uF
C134 "Capacitor" 0402L 2251.32,703.67 r270 top value=15pF
C135 "T521D336M035ATE065" 7343-31 3862.48,641.03 r90 top value=33uF
C136 "Capacitor" 1206_180 3574.32,652.08 r90 top value=10uF
C137 "Capacitor" 1206_180 3682.78,654.05 r90 top value=10uF
C138 "Capacitor" 0603L 1841.56,709.58 r270 top value=100pF
C139 "GCM155R71H104KE02D" 0402 1534.71,3219.41 r270 top value=0.1uF
C140 "Capacitor" 0603L 1956.01,673.39 r270 top value=100pF
C141 "GRM1885C1E112JA01D" 0603 4192.09,4127.82 r180 top value=1100pF
C142 "GRM188Z71A106MA73D" 0603 3175.78,4467.36 r90 top value=10uF
C143 "C0603X104K8RACTU" 0603 3236.3,4467.36 r90 top value=0.1uF
C144 "885012106017" 0603S 2966.27,4330.92 r90 top value=1uF
C145 "GCM188R71C104KA37J" 0603S 2913.44,4331.52 r90 top value=0.1uF
C146 "06035A120JAT2A" 0603S 3306.82,4456.06 r90 top value=12pF
C147 "06035A120JAT2A" 0603S 3362.13,4456.06 r90 top value=12pF
C148 "C1608X5R1E106M080AC" 0603S 597,4157.42 r90 top value=10uF
C149 "C1608X5R1E106M080AC" 0603S 653.01,4157.42 r90 top value=10uF
C150 "C0603C105K3RACTU" 0603S 709.31,4157.42 r90 top value=1uF
C151 "C1608X5R1E106M080AC" 0603S 1140.15,4190.67 r270 top value=10uF
C152 "C1608X5R1E106M080AC" 0603S 1197.63,4190.67 r270 top value=10uF
C153 "C0603C105K3RACTU" 0603S 1255.12,4190.67 r270 top value=1uF
C154 "GCM155R71H104KE02D" 0402 1703.34,3195.78 r270 top value=0.1uF
C155 "T521D336M035ATE065" 7343-31 3622.03,3027.59 r270 top value=33uF
C156 "T521D336M035ATE065" 7343-31 3854.93,3027.59 r270 top value=33uF
C157 "C0603C104K9RAC7867" 0603 1290.46,3004.32 r270 top value=0.1uF
D1 "SMCJ22CA-TR" SMC_Bi 1341.78,3542.22 r90 top value=22V
D2 "BAS40-04-7-F" SOT-23L 2952.76,3567.45 r90 top value=40V
D3 "BAS40-04-7-F" SOT-23L 1053.15,3011.81 r90 top value=40V
D4 "BAS40-04-7-F" SOT-23L 1370.08,3145.51 r0 top value=40V
D5 "B220A-13-F" SMA 4218.97,2077.54 r90 top value=20V
D6 "150060VS75000" WL-SMCW_GREEN 1835,1840.2 r0 top value=Green
D7 "B220A-13-F" SMA 4065.78,616.02 r90 top value=20V
D8 "150060VS75000" WL-SMCW_GREEN 1771.77,490.1 r0 top value=Green
D9 "150060VS75000" WL-SMCW_GREEN 3993.93,4845.01 r270 top value=Green
D10 "B150-13-F" SMA 2896.45,1659.07 r270 top value=50V
D11 "150060VS75000" WL-SMCW_GREEN 3867.55,4849.1 r270 top value=Green
GND "5015" Testpoint_Keystone_Miniature 4609.54,1240.16 r180 top
ILIM "5012" Keystone5012 4277.02,3480.63 r0 top
IN_ISNS "5012" Keystone5012 2491.8,4077.74 r0 top
J1 "Receptacle_2x1" On-Shore_ED120_2DS 497.47,3557.22 r90 top
J2 "Receptacle_2x1" On-Shore_ED120_2DS 4688.18,1974.88 r90 top
J3 "Receptacle_2x1" On-Shore_ED120_2DS 4609.54,476.1 r90 top
J4 "SBH11-PBPC-D07-ST-BK" CONN_SBH11-PBPC-D07-ST-BK 4477.66,4454.17 r90 top
J5 "PEC03SAAN" CONN_PEC03SAAN 2702.65,5157.48 r180 top
J6 "TSW-106-07-G-D" TSW-106-07-G-D 1584.11,5005.64 r180 top
J7 "PEC03SAAN" CONN_PEC03SAAN 3389.63,5157.48 r0 top
J8 "PEC03SAAN" CONN_PEC03SAAN 482.28,4130.59 r90 top
J9 "TSW-102-07-G-S" TSW-102-07-G-S 331.13,4611.16 r90 top
J10 "Receptacle_2x1" On-Shore_ED120_2DS 4686.27,3148.49 r90 top
J11 "HTSW-102-07-G-D" FP-HTSW-102-07-G-D_HDR4-MFG 4547.66,3804.79 r0 top
J12 "PJ-098H" FP-PJ-098H_PTH_CONN_8MM0_12MM0-MFG 544.79,3120.08 r0 top
L1 "744307016" WE-HCM_7070 1659.86,3832.21 r0 top value=160nH
L2 "BMRHDY1010302R2MA1" FP-BMRHDY1010302R2MA1_SMT_IND_11MM2_10MM1-MFG 2081.35,2748.24 r0 top
L3 "BMRHDY1010302R2MA1" FP-BMRHDY1010302R2MA1_SMT_IND_11MM2_10MM1-MFG 2075.78,1373.06 r0 top
L4 "LPS4012-103MLB" LPS4012 1002.35,4175.47 r90 top value=10uH
Logo1 "Texas Instruments" TI_Stacked_Overlay_Small 4572.14,5242.34 r0 top
Logo2 "FCC disclaimer" FCC_disclaimer 875.98,5324.8 r0 top
LOGO3 "CE Mark" CE_Mark_5mm 344.49,467.55 r0 top
MUX_PWR "5010" Keystone5010 2396.28,2989.44 r0 top
Q1 "CSD17581Q3A" DNH0008A 1936.18,3593.14 r0 top value=30V
Q2 "CSD17578Q3A" DNH0008A 2139.9,3593.14 r180 top value=30V
Q3 "CSD17581Q3A" DNH0008A 2783.94,422.92 r180 top value=30V
Q4 "CSD17581Q3A" DNH0008A 3126.72,2117.08 r270 top value=30V
Q5 "CSD17578Q3A" DNH0008A 3108.81,1953.28 r0 top value=30V
Q6 "CSD17578Q3A" DNH0008A 1712.47,2559.68 r270 top value=30V
Q7 "CSD17578Q3A" DNH0008A 1707.85,2721.55 r0 top value=30V
Q8 "CSD17578Q3A" DNH0008A 2442.14,2724.15 r180 top value=30V
Q9 "CSD17578Q3A" DNH0008A 2423.72,2552.92 r270 top value=30V
Q10 "SISS27ADN-T1-GE3" FP-SISS27ADN-T1-GE3_PowerPAK1212-8S-MFG 3472.5,2125.34 r270 top
Q11 "CSD17578Q3A" DNH0008A 2346.71,3567.45 r0 top value=30V
Q12 "NX3020NAKW,115" SOT-323 1643.07,1745.13 r90 top value=30V
Q13 "CSD17578Q3A" DNH0008A 1716.47,1131.71 r270 top value=30V
Q14 "CSD17578Q3A" DNH0008A 1707.71,1325.41 r0 top value=30V
Q15 "CSD17578Q3A" DNH0008A 2447.57,1325.41 r180 top value=30V
Q16 "CSD17578Q3A" DNH0008A 2420.57,1057.55 r270 top value=30V
Q17 "SISS27ADN-T1-GE3" FP-SISS27ADN-T1-GE3_PowerPAK1212-8S-MFG 3356.3,711.8 r270 top
Q18 "NX3020NAKW,115" SOT-323 3865.58,5150.58 r270 top value=30V
Q19 "NX3020NAKW,115" SOT-323 1580.95,392 r90 top value=30V
Q20 "NX3020NAKW,115" SOT-323 3995,5153.46 r270 top value=30V
Q21 "BC817-16LT1G" SOT-23 3041.82,1678.75 r0 top value="45 V"
R1 "PMR18EZPFV2L00" 1206 2015.01,3729.55 r180 top value=0.002
R2 "PMR18EZPFV2L00" 1206 2608.94,3593.14 r180 top value=0.002
R3 "Resistor" 0603L 3027.14,3789.04 r180 top value=4.99
R4 "Resistor" 0603L 3027.14,3842.19 r180 top value=4.99
R5 "RC0603FR-07100KL" 0603 1013.78,3139.76 r90 top value=100k
R6 "RT0603BRD071K15L" 0603 1701.76,3324.44 r90 top value=1.15k
R7 "RC0603FR-07280KL" 0603 4116.53,3626.45 r0 top value=280k
R8 "CRCW060368R1FKEA" 0603 1597,3216.52 r90 top value=68.1
R9 "RC0603FR-07100KL" 0603 4118,3700.04 r0 top value=100k
R10 "Resistor" 0603L 2026.64,3980.45 r180 top value=4.99
R11 "Resistor" 0603L 2026.64,4035.04 r0 top value=4.99
R12 "RC0603FR-07100KL" 0603 4030.34,3860.19 r0 top value=100k
R13 "RC0603FR-07100KL" 0603 4324.57,3822.97 r270 top value=100k
R14 "RC0603FR-07100KL" 0603 3081.77,3594.55 r0 top value=100k
R15 "RC0603FR-0722K6L" 0603 2867.59,3664.16 r180 top value=22.6k
R16 "RC0603FR-07100KL" 0603 1318.9,4280.52 r270 top value=100k
R17 "RC0603FR-072K7L" 0603 2998.19,3664.16 r180 top value=2.70k
R19 "RC0603FR-07100KL" 0603 3577.4,3686.59 r0 top value=100k
R20 "RT0603DRE075K97L" 0603 2869.38,2300.77 r270 top value=5.97k
R21 "RC0603FR-07715RL" 0603 2710.82,2332.27 r0 top value=715
R22 "RT0603BRD071K13L" 0603 1334.11,5187.01 r90 top value=1.13k
R23 "WSLP12065L000FEA" 1206 3681.42,1917.38 r0 top value=0.005
R24 "WSLP12065L000FEA" 1206 1477.62,2464.89 r0 top value=0.005
R25 "5106" 5106 3615.36,2137.34 r270 top value=0
R26 "Resistor" 0603L 1426.44,2306.84 r90 top value=4.99
R27 "Resistor" 0603L 1746.17,2435.51 r0 top value=56
R28 "Resistor" 0603L 3653.86,1722.5 r90 top value=10
R29 "Resistor" 0603L 3715.87,1722.5 r90 top value=10
R30 "Resistor" 0603L 1484.38,2306.84 r90 top value=4.99
R31 "Resistor" 0603L 2205.43,2556.52 r180 bottom value=56
R32 "Resistor" 0805_HV 1373.04,1999.95 r180 top value=1.0
R33 "CRCW040215K0FKED" 0402L 2231.4,2126.02 r270 top value=15.0k
R34 "Resistor" 0402L 2181.95,2080.13 r90 top value=40.2k
R35 "CRCW060310R0JNEA" 0603L 1717.74,1984.31 r90 top value=10
R36 "CRCW20100000Z0EF" 2010 4372.75,2068.38 r90 top value=0
R37 "CRCW060333K0JNEA" 0603L 1613.45,1985.44 r90 top value=33k
R38 "Resistor" 0603L 2058.33,2058.11 r270 top value=10.0k
R39 "Resistor" 0603L 2058.33,1947.89 r90 top value=10.0k
R40 "RC0603FR-07100KL" 0603L 1544.8,1985.45 r270 top value=100k
R41 "RT0603BRD071K13L" 0603 1270.67,4824.8 r270 top value=1.13k
R42 "CRCW0603191KFKEA" 0603L 1784.92,2105.35 r90 top value=191k
R43 "CRCW0603100KFKEA" 0603L 1895.93,2076.81 r90 top value=100k
R44 "Resistor" 0603L 2003.21,2058.11 r270 top value=30.1k
R45 "RC0603FR-074K3L" 0603 2834.54,5043.46 r0 top value=4.30k
R46 "RC0603FR-07220RL" 0603 1674.57,1840.2 r0 top value=220
R47 "WSLP12065L000FEA" 1206 3510.16,495.89 r0 top value=0.005
R48 "WSLP12065L000FEA" 1206 1441.72,1054.66 r0 top value=0.005
R49 "5106" 5106 3479.21,717.41 r270 top value=0
R50 "Resistor" 0603L 1418.07,928.96 r90 top value=4.99
R51 "Resistor" 0603L 1775.95,1001.1 r0 top value=56
R52 "Resistor" 0603L 3482.6,330.91 r90 top value=10
R53 "Resistor" 0603L 3537.72,330.91 r90 top value=10
R54 "Resistor" 0603L 1477.13,928.96 r90 top value=4.99
R55 "Resistor" 0603L 2220.78,1232.55 r0 bottom value=56
R56 "Resistor" 0805_HV 1383.65,642.84 r180 top value=1.0
R57 "CRCW040215K0FKED" 0402L 2207,758.56 r270 top value=15.0k
R58 "Resistor" 0402L 2157.78,699.58 r90 top value=40.2k
R59 "CRCW060310R0JNEA" 0603L 1711.62,624.53 r90 top value=10
R60 "CRCW20100000Z0EF" 2010 4233.92,606.1 r90 top value=0
R61 "CRCW060333K0JNEA" 0603L 1617.04,624.53 r90 top value=33k
R62 "Resistor" 0603L 2065.26,662.33 r270 top value=10.0k
R63 "Resistor" 0603L 2065.26,553.07 r90 top value=10.0k
R64 "RC0603FR-07100KL" 0603L 1562.79,624.53 r270 top value=100k
R65 "RC0603FR-074K3L" 0603 2667.32,5043.46 r180 top value=4.30k
R66 "CRCW0603191KFKEA" 0603L 1785.45,709.58 r90 top value=191k
R67 "CRCW0603100KFKEA" 0603L 1901.92,673.39 r90 top value=100k
R68 "Resistor" 0603L 2011.13,662.33 r270 top value=30.1k
R69 "RMCF0603ZT0R00" 0603 2815.84,4486.06 r270 top value=0
R70 "RC0603FR-07220RL" 0603 1615.4,490.1 r0 top value=220
R71 "RMCF0603ZT0R00" 0603 4192.91,4256.82 r0 top value=0
R72 "RC0603FR-0747KL" 0603 4192.09,4191.86 r180 top value=47.0k
R73 "RC0603FR-074K3L" 0603 3255,5047.29 r180 top value=4.30k
R74 "RC0603FR-074K3L" 0603 3422.89,5047.29 r0 top value=4.30k
R75 "RC0603FR-074K3L" 0603 1734.11,5187.01 r90 top value=4.30k
R76 "RC0603FR-074K3L" 0603 1634.11,5187.01 r90 top value=4.30k
R77 "RC0603FR-074K3L" 0603 1434.11,5185.13 r90 top value=4.30k
R78 "RC0603FR-074K3L" 0603 1534.11,5185.13 r90 top value=4.30k
R79 "RC0603FR-074K3L" 0603 1633.88,4824.8 r270 top value=4.30k
R80 "RC0603FR-074K3L" 0603 1734.11,4824.8 r270 top value=4.30k
R81 "RC0603FR-074K3L" 0603 1434.11,4824.8 r270 top value=4.30k
R82 "RC0603FR-074K3L" 0603 1534.11,4824.8 r270 top value=4.30k
R83 "RC0603FR-074K3L" 0603 2885.12,4486.06 r90 top value=4.30k
R84 "RT0603DRE0753KL" 0603 2933.07,1938.98 r270 top value=50.0k
R85 "CRCW060317K8FKEA" 0603 1082.68,3139.76 r270 top value=17.8k
R86 "RC0603FR-07220RL" 0603 3995,5006.06 r270 top value=220
R87 "RT0603DRE075K97L" 0603 1764.26,3324.44 r90 top value=5.97k
R88 "RC0603FR-07715RL" 0603 1768.82,3193.17 r90 top value=715
R89 "RC0603FR-0782K5L" 0603 1385.83,4388.79 r180 top value=82.5k
R90 "RC0603FR-07220RL" 0603 3865.58,5006.06 r270 top value=220
R91 "RT0603BRD0754K9L" 0603 1270.67,5187.01 r270 top value=54.9k
R92 "RT0603BRD0754K9L" 0603 1334.11,4824.8 r90 top value=54.9k
R93 "RMCF0603ZT0R00" 0603 2934.06,4162.34 r180 top value=0
R94 "RMCF0603ZT0R00" 0603 2934.06,4227.3 r180 top value=0
R95 "CRCW06033M57FKEA" 0603 1417.32,4319.89 r0 top value=3.57Meg
R96 "RC0603FR-07100KL" 0603 1468.18,3241.98 r90 top value=100k
R97 "RC0603FR-07100KL" 0603 1536.52,2935.42 r90 top value=100k
R99 "CRCW060317K8FKEA" 0603 1468.18,3114.01 r90 top value=17.8k
R100 "RC0603FR-0782K5L" 0603 1467.63,2935.42 r270 top value=82.5k
R101 "CRCW06033M57FKEA" 0603 1369.2,2886.21 r180 top value=3.57Meg
R103 "RMCF0603ZT0R00" 0603 1754.84,3422.29 r0 top value=0
R104 "RMCF0603ZT0R00" 0603 3623.39,3856.48 r90 top value=0
R105 "RMCF0603ZT0R00" 0603 3687.98,3856.48 r90 top value=0
R106 "RMCF0603ZT0R00" 0603 3561.65,3856.48 r90 top value=0
R107 "RMCF0603ZT0R00" 0603 3096.25,5256.58 r90 top value=0
R108 "RMCF0603ZT0R00" 0603 3032.48,5255.91 r90 top value=0
R109 "RMCF0603ZT0R00" 0603 2807.64,2300.77 r270 top value=0
SYS_IAVG "5012" Keystone5012 3937.01,3480.63 r90 top
SYS_IFLT "5012" Keystone5012 3482.3,3480.63 r90 top
SYS_ISNS "5012" Keystone5012 3645.99,3480.63 r0 top
TP1 "UCB1SDA" Keystone5012 2791.32,5305.12 r0 top
TP2 "UCB0SDA" Keystone5012 3303.45,5305.12 r0 top
TP3 "UCB1SCL" Keystone5012 2627.95,5305.12 r0 top
TP4 "UCB0SCL" Keystone5012 3475.39,5305.12 r0 top
TP5 "TP_SM_1MM" TP_SM_1MM 1597,3305.74 r90 top
TP6 "TP_SM_1MM" TP_SM_1MM 1846.99,3224.66 r90 top
TP7 "TP_SM_1MM" TP_SM_1MM 2943.14,2280.22 r90 top
TP8 "TP_SM_1MM" TP_SM_1MM 2807.64,2395.07 r90 top
TP9 "TP_SM_1MM" TP_SM_1MM 2735.79,2187.94 r90 top
TP10 "TP_SM_1MM" TP_SM_1MM 1505.91,4319.89 r270 top
TP11 "TP_SM_1MM" TP_SM_1MM 1279.53,2890.14 r90 top
TP12 "5011" Keystone5011 4688.18,1669.19 r0 top
TP13 "5011" Keystone5011 531.5,2539.56 r0 top
TP14 "5011" Keystone5011 929.52,4992.47 r0 top
TP15 "5011" Keystone5011 1042.22,414.64 r0 top
TP17 "5011" Keystone5011 4686.27,2830.14 r0 top
U1 "LM74800" DRR0012E-MFG 1910.89,3395.07 r0 top
U2 "INA213BIDCKR" DCK0006A_N 3223.7,3803.81 r180 top
U3 "TLV9051IDBVR" DBV0005A-MFG 4182.9,3822.78 r180 top
U4 "INA213BIDCKR" DCK0006A_N 2214.82,3984.33 r180 top
U5 "LM74700QDBVRQ1" DBV0006A_N 2811.56,593.69 r270 top
U6 "TLV9051IDBVR" DBV0005A-MFG 3236.3,3552.5 r180 top
U7 "LM74800" DRR0012E-MFG 2879.22,2133.46 r270 top
U8 "TLV9051IDBVR" DBV0005A-MFG 3737.83,3630.49 r180 top
U9 "BQ25731RSN" RSN0032B-MFG 2085.89,2291.39 r0 top
U10 "BQ25731RSN" RSN0032B-MFG 2084.09,903.66 r0 top
U11 "MSP430FR2475TRHBR" RHB0032E 3356.03,4256.82 r0 top
U12 "PCA9546ARGVR" RGV0016A 2774.5,4310.15 r270 top
U13 "TPS62177DQCR" DQC0010A 804.52,4117.36 r0 top
U14 "TLV7031DCKR" DCK0005A_N 1417.32,4211.63 r270 top
U15 "TLV7031DCKR" DCK0005A_N 1379.04,2994.47 r90 top
VBAT_A "5010" Keystone5010 3467.5,1754.44 r0 top
VBAT_B "5010" Keystone5010 3276.93,344.68 r0 top
VDDA_A "5010" Keystone5010 492.13,1801.66 r180 top
VDDA_B "5010" Keystone5010 1295.49,424.74 r180 top
Vin "5010" Keystone5010 661.86,3868.11 r0 top
VIN_FLT "5010" Keystone5010 1879.92,4076.52 r90 top
Vin_PROT "5010" Keystone5010 531.5,2746.06 r0 top (schematic designator VIN_PROT)
VSYS "5010" Keystone5010 4674.07,3454.2 r0 top
Y1 "ABS07-32.768KHZ-T" XTAL_ABS07 3336.49,4583.23 r0 top
ZZ1 "This Assembly Note is for PCB labels only" AssemblyNoteLabel 322.8,7628.94 r0 top
ZZ2 "These assemblies are ESD sensitive, ESD precautions shall be observed." AssemblyNote 322.8,7520.06 r0 top
ZZ3 "These assemblies must be clean and free from flux and all contaminants. Use of no clean flux is not acceptable." AssemblyNote 322.8,7431.5 r0 top
ZZ4 "These assemblies must comply with workmanship standards IPC-A-610 Class 2, unless otherwise specified." AssemblyNote 322.8,7342.94 r0 top

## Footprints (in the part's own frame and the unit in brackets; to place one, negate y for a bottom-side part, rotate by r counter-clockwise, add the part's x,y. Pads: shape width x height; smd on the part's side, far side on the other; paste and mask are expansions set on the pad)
0402 [mm] "0402 from SM-752 data"
  rect 0.8x0.6 smd: 1(-0.6,0) 2(0.6,0)
  silkscreen extent -1.22,-0.52 1.22,0.52, body extent -0.55,-0.3 0.55,0.3, height 0.6
0402L [mm] "0402 from SM-752 data"
  rect 0.6x0.5 smd: 1(-0.5,0) 2(0.5,0)
  body extent -0.55,-0.3 0.55,0.3, height 0.6
0603 [mm] "0603 from SM-752 data"
  rect 1x0.95 smd: 1(-0.8,0) 2(0.8,0)
  silkscreen extent -1.52,-0.69 1.52,0.69, body extent -0.87,-0.47 0.87,0.47, height 1
0603L [mm] "0603 from SM-752 data"
  rect 0.8x0.85 smd: 1(-0.7,0) 2(0.7,0)
  silkscreen extent -0.07,-0.33 0.07,0.33, body extent -0.87,-0.47 0.87,0.47, height 1
0603S [mil]
  rect 20x35 smd: 1(-30,0) 2(30,0)
  body extent -34,-19 34,19, height 39
0805_HV [mil] "0805 with 30mil clearance between pads"
  rect 50x63 smd: 1(-40,0) 2(40,0)
  silkscreen extent -74,-40 74,40, body extent -43,-29 43,29, height 57
0805L [mm] "0805 from SM-752 data"
  rect 1.1x1.4 smd: 1(-0.75,0) 2(0.75,0)
  body extent -1.1,-0.72 1.1,0.72, height 1.45
1206 [mm] "1206 from SM-752 data"
  rect 1.3x1.85 smd: 1(-1.45,0) 2(1.45,0)
  silkscreen extent -2.4,-1.21 2.4,1.21, body extent -1.7,-0.9 1.7,0.9, height 1.35
1206_180 [mm] "1206_180"
  rect 1.1x1.6 smd: 1(-1.7,0) 2(1.7,0)
  silkscreen extent -0.9,-1 0.9,1, body extent -1.75,-0.95 1.75,0.95, height 1.8
2010 [mm] "Chip Capacitor, Body 5.08x2.54mm, IPC Medium Density"
  rect 1.6x2.7 smd: 1(-2.3,0) 2(2.3,0)
  silkscreen extent -3.42,-1.65 3.42,1.65, body extent -2.73,-1.45 2.73,1.45, height 1.66
5106 [mm] "Keystone"
  rect 0.99x1.4 smd: 1(-0.85,0) 2(0.88,0)
  silkscreen extent -1.63,-0.97 1.65,0.97, body extent -1.06,-0.69 1.06,0.69, height 0.84
7343-31 [mm] "Medium Density based on Kemet T495 dimensions"
  rect 2.55x2.45 smd: 1(-3.025,0) 2(3.025,0)
  silkscreen extent -4.56,-2.3 3.8,2.3, body extent -3.8,-2.3 3.8,2.3, height 3.1
AssemblyNote [mil] "Assembly Note"
AssemblyNoteLabel [mil] "Assembly Note for PCB Labels"
CAPSMT_62_F61 [mm] "6.3 x 5.8mm:  Chemi-Con F61"
  rect 3.5x1.6 smd: 1(-2.675,0.025) 2(2.725,0.025)
  silkscreen extent -3.34,-3.38 3.46,3.42, body extent -3.37,-3.38 3.46,3.43, height 6.1
CAPSMT_62_HA0 [mm] "8 x 10mm:  Chemi-Con HA0"
  rect 4.2x2.2 smd: 1(-3.65,0) 2(3.65,0)
  silkscreen extent -4.25,-4.25 4.25,4.25, body extent -4.25,-4.25 4.25,4.25, height 10.5
CE_Mark_5mm [mil] "Minimum text height for CE Mark"
  silkscreen extent -138,-98 138,98
CONN_PEC03SAAN [mm] "SULLINS"
  rect 1.5x1.5 hole 1.016: 1(-2.54,0)
  round 1.5 hole 1.016: 2(0,0) 3(2.54,0)
  silkscreen extent -4.72,-1.27 3.81,1.27, body extent -3.84,-1.3 3.84,1.3, height 8.38
CONN_SBH11-PBPC-D07-ST-BK [mm] "Sullins recommended land pattern"
  rect 1.65x1.65 hole 1.016 mask+0: 1(-7.62,-1.27)
  round 1.65 hole 1.016 mask+0: 2(-7.62,1.27) 3(-5.08,-1.27) 4(-5.08,1.27) 5(-2.54,-1.27) 6(-2.54,1.27) 7(0,-1.27) 8(0,1.27) 9(2.54,-1.27) 10(2.54,1.27) 11(5.08,-1.27) 12(5.08,1.27) 13(7.62,-1.27) 14(7.62,1.27)
  silkscreen extent -12.64,-5.08 12.64,4.7, body extent -12.64,-4.4 12.64,4.7, height 9.12
DBV0005A-MFG [mm]
  rrect17% 1.1x0.6 smd paste+0 mask+0: 1(-1.3,0.95) 2(-1.3,0) 3(-1.3,-0.95) 4(1.3,-0.95) 5(1.3,0.95)
  silkscreen extent -2.58,-1.53 0.87,1.53, body extent -1.95,-1.78 1.95,1.78, height 0.25
DBV0006A_N [mm] "SOT23, 6-Leads, Body 2.9x1.6mm, Pitch 0.95mm, Lead Span 2.8mm, IPC Medium Density"
  rrect17% 1x0.6 smd: 1(-1.375,0.95) 2(-1.375,0) 3(-1.375,-0.95) 4(1.375,-0.95) 5(1.375,0) 6(1.375,0.95)
  silkscreen extent -1.68,-1.55 0.5,1.55, body extent -1.42,-1.46 1.42,1.46, height 1.12
DCK0005A_N [mm] "SOT353, 5-Leads, Body 2x1.3mm, Pitch 0.65mm, Lead Span 2.1mm, IPC Medium Density"
  rrect25% 0.85x0.4 smd: 1(-1.125,0.65) 2(-1.125,0) 3(-1.125,-0.65) 4(1.125,-0.65) 5(1.125,0.65)
  silkscreen extent -1.48,-1.02 0.55,1.1, body extent -1.14,-1 1.14,1, height 0.95
DCK0006A_N [mm] "SOT23, 6-Leads, Body 2x1.3mm, Pitch 0.65mm, Lead Span 2.1mm, IPC Medium Density"
  rrect25% 0.85x0.4 smd: 1(-1.125,0.65) 2(-1.125,0) 3(-1.125,-0.65) 4(1.125,-0.65) 5(1.125,0) 6(1.125,0.65)
  silkscreen extent -1.5,-1.09 0.51,1.09, body extent -1.14,-1 1.14,1, height 0.95
DNH0008A [mm] "VSONP-8"
  rrect50% 0.7x0.4 smd paste-0.05 mask-0.05: 1(-1.55,0.975) 2(-1.55,0.325) 3(-1.55,-0.325) 4(-1.55,-0.975) 5(1.55,-0.975) 6(1.55,-0.325) 7(1.55,0.325) 8(1.55,0.975)
  rrect4% 2.51x2.55 smd paste-1.5 mask-1.5: 9(0.645,0)
  rrect14% 0.705x1.125 on Top Paste: 9A(-0.208,0.662) 9B(0.697,0.662) 9C(-0.208,-0.663) 9D(0.697,-0.663)
  silkscreen extent -1.62,-1.7 1.62,1.7, body extent -1.65,-1.65 1.65,1.66, height 0.91
DQC0010A [mm] "SON, 10-Leads, Body 2x3mm, Pitch 0.5mm, Thermal Pad 2.4x0.84mm"
  rrect40% 0.5x0.25 smd: 1(-0.95,1) 2(-0.95,0.5) 3(-0.95,0) 4(-0.95,-0.5) 5(-0.95,-1) 6(0.95,-1) 7(0.95,-0.5) 8(0.95,0) 9(0.95,0.5) 10(0.95,1)
  rrect12% 0.8x1.08 on Top Paste: 11(0,-0.64) 11(0,0.64)
  rrect12% 0.84x2.4 smd paste-0.42: 11(0,0)
  silkscreen extent -1.18,-1.68 1.17,1.68, body extent -1,-1.5 1,1.5, height 0.77
DRR0012E-MFG [mm]
  rrect40% 0.62x0.25 smd paste+0 mask+0: 1(-1.39,1.25) 2(-1.39,0.75) 3(-1.39,0.25) 4(-1.39,-0.25) 5(-1.39,-0.75) 6(-1.39,-1.25) 7(1.39,-1.25) 8(1.39,-0.75) 9(1.39,-0.25) 10(1.39,0.25) 11(1.39,0.75) 12(1.39,1.25)
  rrect8% 1.3x2.5 smd paste-1000 mask+0: 13(0,0)
  silkscreen extent -2.37,-1.75 1.55,1.75, body extent -1.8,-1.65 1.8,1.65, height 0.25
FCC_disclaimer [mil]
FP-BMRHDY1010302R2MA1_SMT_IND_11MM2_10MM1-MFG [mm]
  rrect3% 3.5x4 smd paste+0 mask+0: 1(-4.75,0) 2(4.75,0)
  silkscreen extent -5.75,-5.2 5.75,5.2, body extent -6.6,-5.3 6.6,5.3, height 0.25
FP-HTSW-102-07-G-D_HDR4-MFG [mm]
  rrect7% 1.52x1.52 hole 1.02 paste-1000 mask+0: 1(-1.27,-1.27)
  round 1.52 hole 1.02 paste-1000 mask+0: 2(-1.27,1.27) 3(1.27,-1.27) 4(1.27,1.27)
  body extent -2.7,-2.68 2.7,2.68, height 0.25
FP-PJ-098H_PTH_CONN_8MM0_12MM0-MFG [mm]
  rrect100% 1.9x1.4 hole 0.8 slot 1.3 at 0 deg paste-1000 mask+0: 1(5.6,-2.3)
  rrect100% 2.6x1.4 hole 0.8 slot 2 at 0 deg paste-1000 mask+0: 2(-2.4,-3.9) 2(-2.4,3.9) 2(2.9,-3.9) 2(2.9,3.9) 3(5.25,1.12)
  silkscreen extent -6.1,-4.1 7.23,4.1, body extent -6.2,-4.7 6.65,4.7, height 0.25
FP-SISS27ADN-T1-GE3_PowerPAK1212-8S-MFG [mil]
  rrect25% 39x16 smd paste+0 mask+0: 1(-56.5,39) 2(-56.5,13) 3(-56.5,-13) 4(-56.5,-39)
  round 59.4 smd paste+0 mask+0: 5-6-7-8(21,8)
  Top Layer region: 76,47 46,47 46,44 -12,44 -12,-44 46,-44 46,-47 76,-47 76,-31 56,-31 56,-21 76,-21 76,-5 56,-5 56,5 76,5 76,21 56,21 56,31 76,31 76,47
  silkscreen extent -103,-67 67,67, body extent -80,-71 80,71, height 10
KCM55W [mm] "MuRata"
  rect 2.7x5.6 smd: 1(-2.65,0) 2(2.65,0)
  silkscreen extent -1.05,-2.8 1,2.8, body extent -3.25,-2.75 3.25,2.75, height 6.7
Keystone5010 [mil] "Keystone Multipurpose loops"
  round 87 hole 63: 1(0,0)
  silkscreen extent -70,-70 70,70, body extent -63,-63 63,62, height 319
Keystone5011 [mil] "Keystone Multipurpose loops"
  round 87 hole 63: 1(0,0)
  silkscreen extent -70,-70 70,70, body extent -63,-63 63,62, height 319
Keystone5012 [mil] "Keystone Multipurpose loops"
  round 87 hole 63: 1(0,0)
  silkscreen extent -70,-70 70,70, body extent -63,-63 63,62, height 319
LPS4012 [mm] "Coilcraft recommended land pattern.  Document 433-2, rev 10/20/08"
  rect 0.7x3.124 smd: 1(-1.881,0) 2(1.881,0)
  rect 0.902x0.801 smd rot 45: 1(-1.592,1.605) 2(1.592,-1.605)
  rect 0.902x0.801 smd rot 135: 1(-1.592,-1.605) 2(1.592,1.605)
  rect 0.812x0.7 smd: 1(-1.168,1.85) 1(-1.168,-1.85) 2(1.168,1.85) 2(1.168,-1.85)
  silkscreen extent -3.26,-2.6 2.55,2.6, body extent -2.05,-2.05 2.05,2.05, height 1.22
On-Shore_ED120_2DS [mm] "ONSHORE"
  rrect5% 2x2 hole 1.25: 1(-2.54,0)
  round 2 hole 1.25: 2(2.54,0)
  silkscreen extent -5.6,-4 5.12,5, body extent -5.78,-4 5.08,5, height 13
RGV0016A [mm] "QFN, 16-Leads, Body 4x4mm, Pitch 0.65mm, Thermal Pad 2.16x2.16mm, TI Recommended"
  rrect33% 0.75x0.3 smd: 1(-1.825,0.975) 2(-1.825,0.325) 3(-1.825,-0.325) 4(-1.825,-0.975) 9(1.825,-0.975) 10(1.825,-0.325) 11(1.825,0.325) 12(1.825,0.975)
  rrect33% 0.3x0.75 smd: 5(-0.975,-1.825) 6(-0.325,-1.825) 7(0.325,-1.825) 8(0.975,-1.825) 13(0.975,1.825) 14(0.325,1.825) 15(-0.325,1.825) 16(-0.975,1.825)
  rrect11% 0.939x0.939 on Top Paste: 17(-0.569,0.57) 17(-0.569,-0.569) 17(0.57,0.57) 17(0.57,-0.569)
  rrect5% 2.1x2.1 smd paste-1.08: 17(0,0)
  silkscreen extent -2.22,-2.22 2.23,2.23, body extent -2.07,-2.07 2.08,2.08, height 1.01
RHB0032E [mm] "QFN, 32-Leads, Body 5x5mm, Pitch 0.5mm, Thermal Pad 3.45x3.45mm, TI Recommended"
  rrect40% 0.6x0.25 smd: 1(-2.4,1.75) 2(-2.4,1.25) 3(-2.4,0.75) 4(-2.4,0.25) 5(-2.4,-0.25) 6(-2.4,-0.75) 7(-2.4,-1.25) 8(-2.4,-1.75) 17(2.4,-1.75) 18(2.4,-1.25) 19(2.4,-0.75) 20(2.4,-0.25) 21(2.4,0.25) 22(2.4,0.75) 23(2.4,1.25) 24(2.4,1.75)
  rrect40% 0.25x0.6 smd: 9(-1.75,-2.4) 10(-1.25,-2.4) 11(-0.75,-2.4) 12(-0.25,-2.4) 13(0.25,-2.4) 14(0.75,-2.4) 15(1.25,-2.4) 16(1.75,-2.4) 25(1.75,2.4) 26(1.25,2.4) 27(0.75,2.4) 28(0.25,2.4) 29(-0.25,2.4) 30(-0.75,2.4) 31(-1.25,2.4) 32(-1.75,2.4)
  rrect3% 3.45x3.45 smd paste-1.725: 33(0,0)
  rrect7% 1.49x1.49 on Top Paste: ""(-0.845,-0.845) ""(-0.845,0.845) ""(0.845,-0.845) ""(0.845,0.845)
  silkscreen extent -2.72,-2.73 2.72,2.73, body extent -2.57,-2.57 2.58,2.58, height 1.01
RSN0032B-MFG [mm]
  round 0.18 smd paste+0 mask+0: 1(-2.01,1.4) 2(-2.01,1) 3(-2.01,0.6) 4(-2.01,0.2) 5(-2,-0.2) 6(-2,-0.6) 7(-2,-1) 8(-2,-1.4) 9(-1.4,-2.01) 10(-1,-2.01) 11(-0.6,-2.01) 12(-0.2,-2.01) 13(0.2,-2) 14(0.6,-2) 15(1,-2) 16(1.4,-2) 17(2.01,-1.4) 18(2.01,-1) 19(2.01,-0.6) 20(2.01,-0.2) 21(2,0.2) 22(2,0.6) 23(2,1) 24(2,1.4) 25(1.4,2.01) 26(1,2.01) 27(0.6,2.01) 28(0.2,2.01) 29(-0.2,2) 30(-0.6,2) 31(-1,2) 32(-1.4,2)
  rrect4% 2.8x2.8 smd paste-1000 mask+0: 33(0,0)
  Top Layer region: -1.3,2.4 -1.3,1.7 -1.313,1.65 -1.35,1.613 -1.4,1.6 -1.4,1.6 -1.438,1.608 -1.471,1.629 -1.492,1.662 -1.5,1.7 -1.5,1.7 -1.5,2.4
  Top Layer region: -0.9,2.4 -0.9,1.7 -0.908,1.662 -0.929,1.629 -0.962,1.608 -1,1.6 -1,1.6 -1.038,1.608 -1.071,1.629 -1.092,1.662 -1.1,1.7 -1.1,1.7 -1.1,2.4
  Top Layer region: -0.5,2.4 -0.5,1.7 -0.508,1.662 -0.529,1.629 -0.562,1.608 -0.6,1.6 -0.6,1.6 -0.638,1.608 -0.671,1.629 -0.692,1.662 -0.7,1.7 -0.7,1.7 -0.7,2.4
  Top Layer region: -0.1,2.4 -0.1,1.7 -0.108,1.662 -0.129,1.629 -0.162,1.608 -0.2,1.6 -0.2,1.6 -0.238,1.608 -0.271,1.629 -0.292,1.662 -0.3,1.7 -0.3,1.7 -0.3,2.4
  Top Layer region: 0.3,2.4 0.3,1.7 0.292,1.662 0.271,1.629 0.238,1.608 0.2,1.6 0.2,1.6 0.162,1.608 0.129,1.629 0.108,1.662 0.1,1.7 0.1,1.7 0.1,2.4
  Top Layer region: 0.7,2.4 0.7,1.7 0.687,1.65 0.65,1.613 0.6,1.6 0.6,1.6 0.562,1.608 0.529,1.629 0.508,1.662 0.5,1.7 0.5,1.7 0.5,2.4
  Top Layer region: 1.1,2.4 1.1,1.7 1.092,1.662 1.071,1.629 1.038,1.608 1,1.6 1,1.6 0.962,1.608 0.929,1.629 0.908,1.662 0.9,1.7 0.9,1.7 0.9,2.4
  Top Layer region: 1.5,2.4 1.5,1.7 1.492,1.662 1.471,1.629 1.438,1.608 1.4,1.6 1.4,1.6 1.362,1.608 1.329,1.629 1.308,1.662 1.3,1.7 1.3,1.7 1.3,2.4
  Top Layer region: 2.4,1.3 1.7,1.3 1.662,1.308 1.629,1.329 1.608,1.362 1.6,1.4 1.6,1.4 1.608,1.438 1.629,1.471 1.662,1.492 1.7,1.5 1.7,1.5 2.4,1.5
  Top Layer region: 2.4,0.9 1.7,0.9 1.662,0.908 1.629,0.929 1.608,0.962 1.6,1 1.6,1 1.608,1.038 1.629,1.071 1.662,1.092 1.7,1.1 1.7,1.1 2.4,1.1
  Top Layer region: 2.4,0.5 1.7,0.5 1.662,0.508 1.629,0.529 1.608,0.562 1.6,0.6 1.6,0.6 1.608,0.638 1.629,0.671 1.662,0.692 1.7,0.7 1.7,0.7 2.4,0.7
  Top Layer region: 2.4,0.1 1.7,0.1 1.662,0.108 1.629,0.129 1.608,0.162 1.6,0.2 1.6,0.2 1.608,0.238 1.629,0.271 1.662,0.292 1.7,0.3 1.7,0.3 2.4,0.3
  Top Layer region: 2.4,-0.3 1.7,-0.3 1.662,-0.292 1.629,-0.271 1.608,-0.238 1.6,-0.2 1.6,-0.2 1.608,-0.162 1.629,-0.129 1.662,-0.108 1.7,-0.1 1.7,-0.1 2.4,-0.1
  Top Layer region: 2.4,-0.7 1.7,-0.7 1.662,-0.692 1.629,-0.671 1.608,-0.638 1.6,-0.6 1.6,-0.6 1.608,-0.562 1.629,-0.529 1.662,-0.508 1.7,-0.5 1.7,-0.5 2.4,-0.5
  Top Layer region: 2.4,-1.1 1.7,-1.1 1.662,-1.092 1.629,-1.071 1.608,-1.038 1.6,-1 1.6,-1 1.608,-0.962 1.629,-0.929 1.662,-0.908 1.7,-0.9 1.7,-0.9 2.4,-0.9
  Top Layer region: 2.4,-1.5 1.7,-1.5 1.662,-1.492 1.629,-1.471 1.608,-1.438 1.6,-1.4 1.6,-1.4 1.608,-1.362 1.629,-1.329 1.662,-1.308 1.7,-1.3 1.7,-1.3 2.4,-1.3
  Top Layer region: 1.3,-2.4 1.3,-1.7 1.308,-1.662 1.329,-1.629 1.362,-1.608 1.4,-1.6 1.4,-1.6 1.438,-1.608 1.471,-1.629 1.492,-1.662 1.5,-1.7 1.5,-1.7 1.5,-2.4
  Top Layer region: 0.9,-2.4 0.9,-1.7 0.908,-1.662 0.929,-1.629 0.962,-1.608 1,-1.6 1,-1.6 1.038,-1.608 1.071,-1.629 1.092,-1.662 1.1,-1.7 1.1,-1.7 1.1,-2.4
  Top Layer region: 0.5,-2.4 0.5,-1.7 0.508,-1.662 0.529,-1.629 0.562,-1.608 0.6,-1.6 0.6,-1.6 0.638,-1.608 0.671,-1.629 0.692,-1.662 0.7,-1.7 0.7,-1.7 0.7,-2.4
  Top Layer region: 0.1,-2.4 0.1,-1.7 0.108,-1.662 0.129,-1.629 0.162,-1.608 0.2,-1.6 0.2,-1.6 0.238,-1.608 0.271,-1.629 0.292,-1.662 0.3,-1.7 0.3,-1.7 0.3,-2.4
  Top Layer region: -0.3,-2.4 -0.3,-1.7 -0.292,-1.662 -0.271,-1.629 -0.238,-1.608 -0.2,-1.6 -0.2,-1.6 -0.162,-1.608 -0.129,-1.629 -0.108,-1.662 -0.1,-1.7 -0.1,-1.7 -0.1,-2.4
  Top Layer region: -0.7,-2.4 -0.7,-1.7 -0.692,-1.662 -0.671,-1.629 -0.638,-1.608 -0.6,-1.6 -0.6,-1.6 -0.562,-1.608 -0.529,-1.629 -0.508,-1.662 -0.5,-1.7 -0.5,-1.7 -0.5,-2.4
  Top Layer region: -1.1,-2.4 -1.1,-1.7 -1.092,-1.662 -1.071,-1.629 -1.038,-1.608 -1,-1.6 -1,-1.6 -0.962,-1.608 -0.929,-1.629 -0.908,-1.662 -0.9,-1.7 -0.9,-1.7 -0.9,-2.4
  Top Layer region: -1.5,-2.4 -1.5,-1.7 -1.492,-1.662 -1.471,-1.629 -1.438,-1.608 -1.4,-1.6 -1.4,-1.6 -1.362,-1.608 -1.329,-1.629 -1.308,-1.662 -1.3,-1.7 -1.3,-1.7 -1.3,-2.4
  Top Layer region: -2.4,-1.3 -1.7,-1.3 -1.662,-1.308 -1.629,-1.329 -1.608,-1.362 -1.6,-1.4 -1.6,-1.4 -1.613,-1.45 -1.65,-1.487 -1.7,-1.5 -1.7,-1.5 -2.4,-1.5
  Top Layer region: -2.4,-0.9 -1.7,-0.9 -1.662,-0.908 -1.629,-0.929 -1.608,-0.962 -1.6,-1 -1.6,-1 -1.608,-1.038 -1.629,-1.071 -1.662,-1.092 -1.7,-1.1 -1.7,-1.1 -2.4,-1.1
  Top Layer region: -2.4,-0.5 -1.7,-0.5 -1.662,-0.508 -1.629,-0.529 -1.608,-0.562 -1.6,-0.6 -1.6,-0.6 -1.608,-0.638 -1.629,-0.671 -1.662,-0.692 -1.7,-0.7 -1.7,-0.7 -2.4,-0.7
  Top Layer region: -2.4,-0.1 -1.7,-0.1 -1.662,-0.108 -1.629,-0.129 -1.608,-0.162 -1.6,-0.2 -1.6,-0.2 -1.608,-0.238 -1.629,-0.271 -1.662,-0.292 -1.7,-0.3 -1.7,-0.3 -2.4,-0.3
  Top Layer region: -2.4,0.3 -1.7,0.3 -1.662,0.292 -1.629,0.271 -1.608,0.238 -1.6,0.2 -1.6,0.2 -1.608,0.162 -1.629,0.129 -1.662,0.108 -1.7,0.1 -1.7,0.1 -2.4,0.1
  Top Layer region: -2.4,0.7 -1.7,0.7 -1.662,0.692 -1.629,0.671 -1.608,0.638 -1.6,0.6 -1.6,0.6 -1.608,0.562 -1.629,0.529 -1.662,0.508 -1.7,0.5 -1.7,0.5 -2.4,0.5
  Top Layer region: -2.4,1.1 -1.7,1.1 -1.662,1.092 -1.629,1.071 -1.608,1.038 -1.6,1 -1.6,1 -1.608,0.962 -1.629,0.929 -1.662,0.908 -1.7,0.9 -1.7,0.9 -2.4,0.9
  Top Layer region: -2.4,1.5 -1.7,1.5 -1.662,1.492 -1.629,1.471 -1.608,1.438 -1.6,1.4 -1.6,1.4 -1.608,1.362 -1.629,1.329 -1.662,1.308 -1.7,1.3 -1.7,1.3 -2.4,1.3
  silkscreen extent -3.1,-2.07 2.07,2.07, body extent -2.5,-2.5 2.5,2.5, height 0.25
SMA [mm] "Molded Diode, 2-Leads, Body 4.3x2.6mm, IPC Medium Density, based on OnSemi component dimensions and land pattern"
  rect 2x2 smd: 1(-2,0) 2(2,0)
  silkscreen extent -3.66,-1.57 2.79,1.57, body extent -2.6,-1.3 2.6,1.3, height 2.42
SMC_Bi [mil] "SMC, no polarity mark"
  rect 110x150 smd: 1(-140.49,0) 2(140.49,0)
  body extent -156,-116 156,116, height 92
SOT-23 [mm] "SOT23, 3-Leads, Body 2.9x1.3mm, Pitch 0.95mm, Lead Span 2.5mm, IPC Medium Density"
  rrect50% 1x0.6 smd: 1(-1.2,0.95) 2(-1.2,-0.95) 3(1.2,0)
  silkscreen extent -1.62,-1.5 0.7,1.5, body extent -1.16,-1.45 1.21,1.45, height 1
SOT-23L [mm] "SOT23, 3-Leads, Body 2.9x1.3mm, Pitch 0.95mm, Lead Span 2.5mm, IPC High Density"
  rrect50% 0.8x0.6 smd: 1(-1.1,0.95) 2(-1.1,-0.95) 3(1.1,0)
  silkscreen extent -1.5,-1.5 0.7,1.5, body extent -1.16,-1.45 1.21,1.45, height 1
